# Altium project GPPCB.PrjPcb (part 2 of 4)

## Sheet Latch1.SchDoc: P.C. BOARD
size A2; Revision: A; SheetNumber: 0; SheetTotal: 0
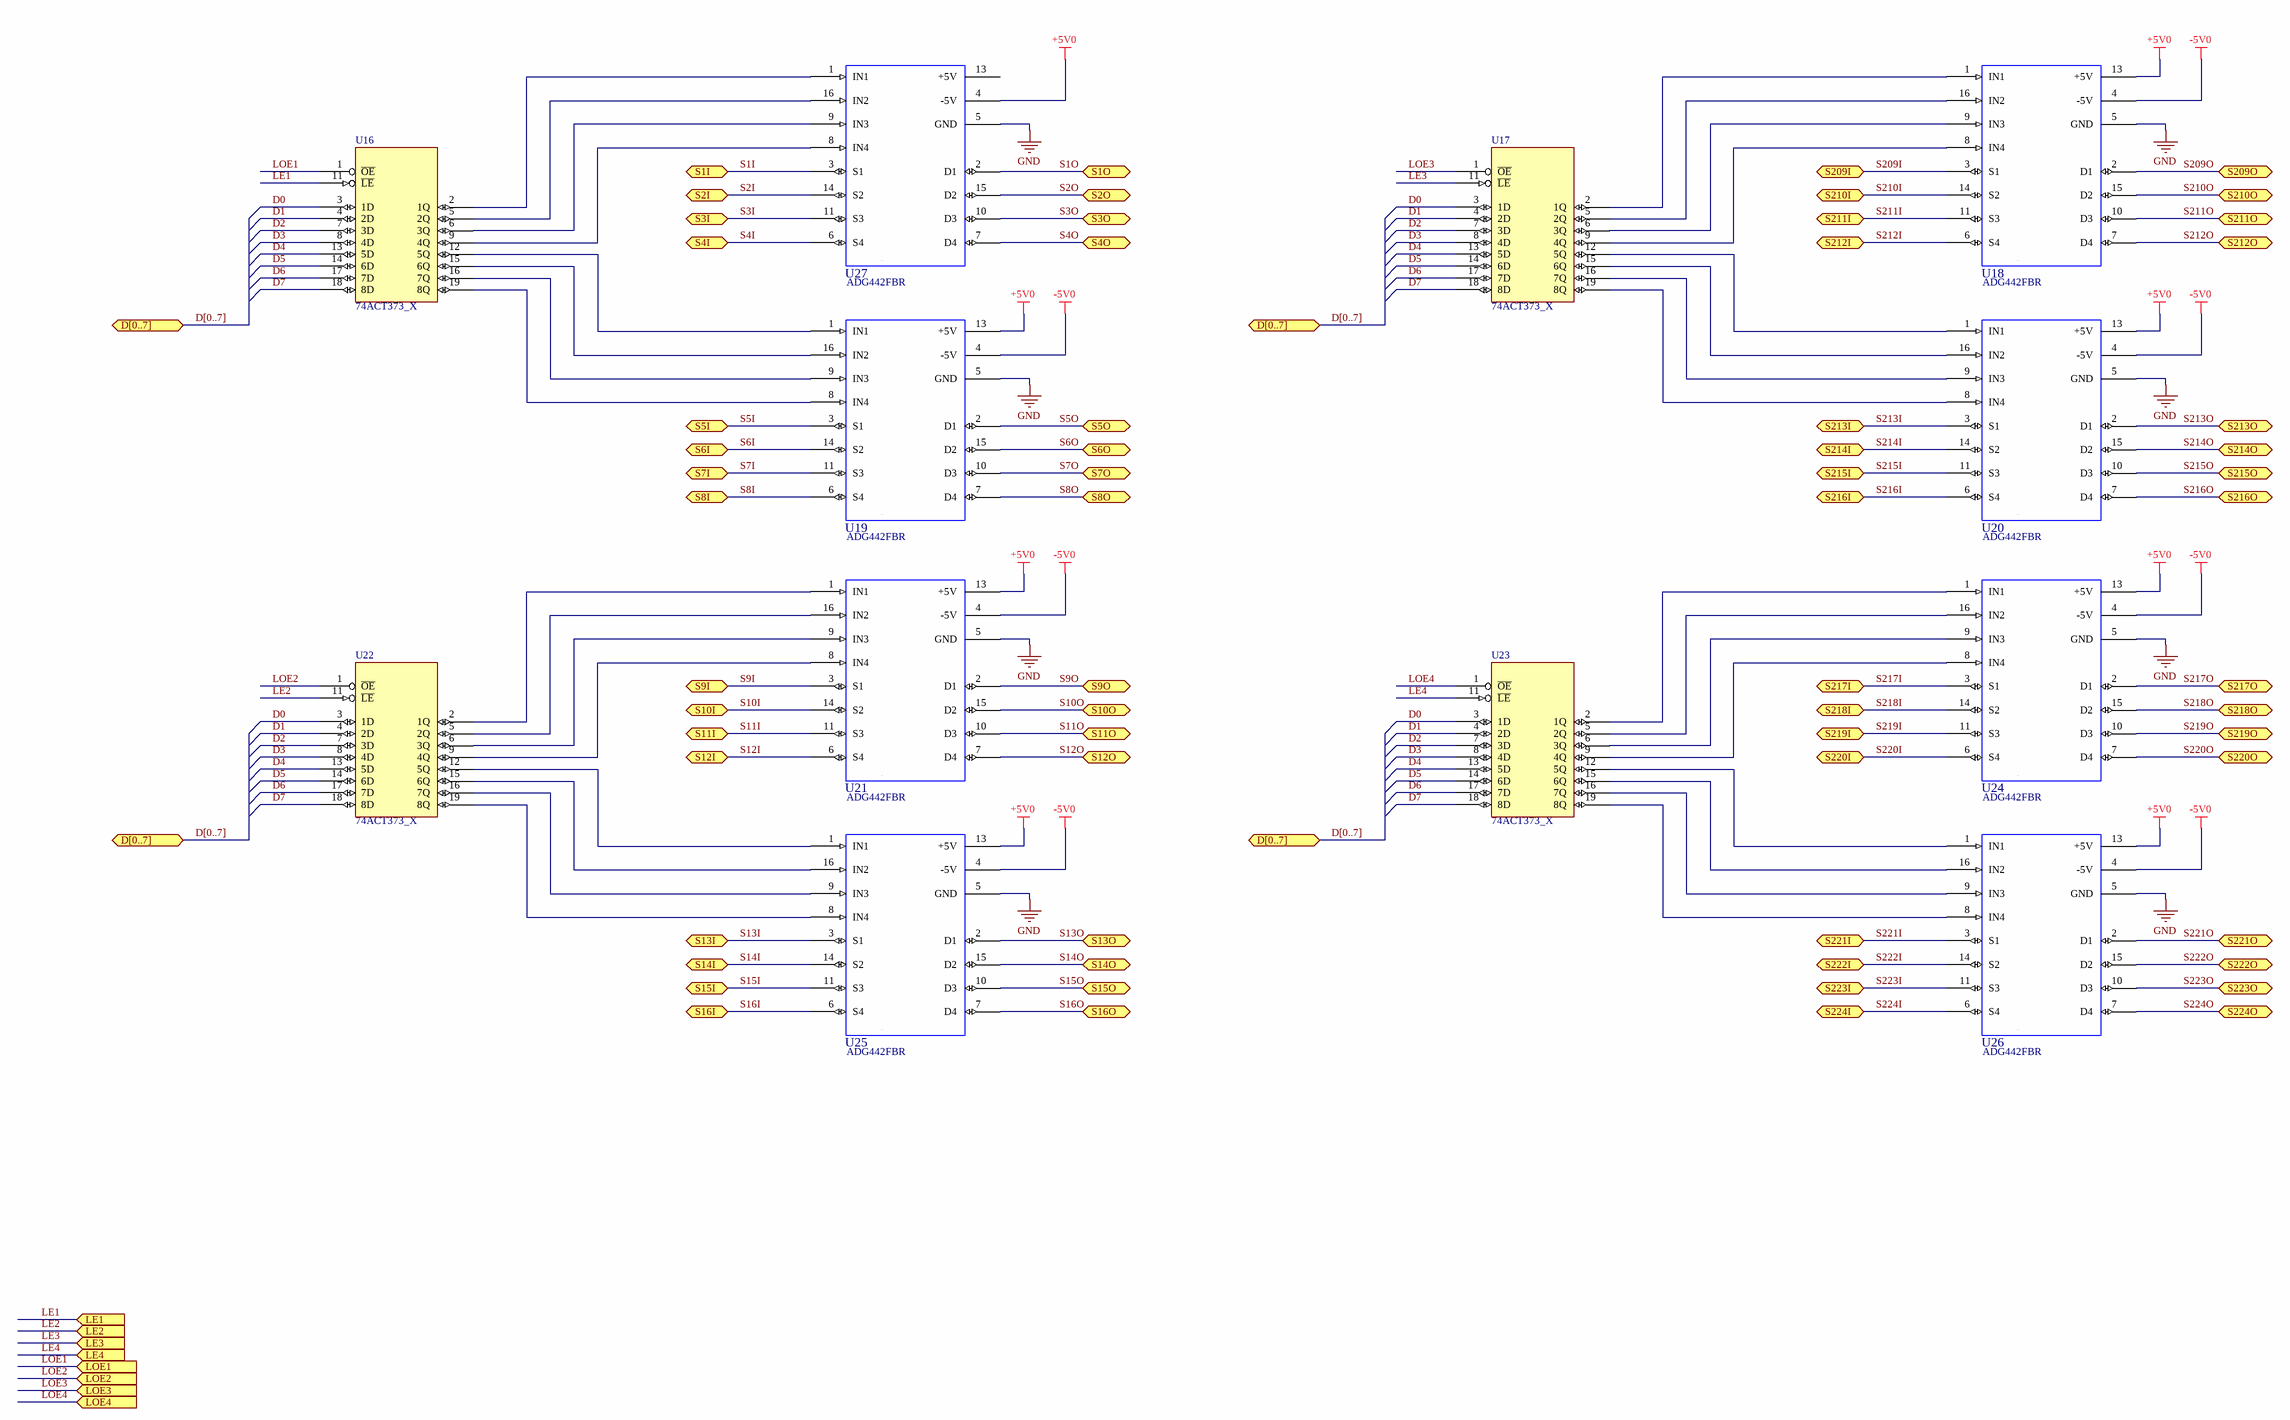
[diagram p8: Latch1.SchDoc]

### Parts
U16  74ACT373_X  [SOL-20/N]
U17  74ACT373_X  [SOL-20/N]
U18  VENDOR PART NO: ADG442FBR  [SO-16/N]  (hidden comment: ADG442)
U19  VENDOR PART NO: ADG442FBR  [SO-16/N]  (hidden comment: ADG442)
U20  VENDOR PART NO: ADG442FBR  [SO-16/N]  (hidden comment: ADG442)
U21  VENDOR PART NO: ADG442FBR  [SO-16/N]  (hidden comment: ADG442)
U22  74ACT373_X  [SOL-20/N]
U23  74ACT373_X  [SOL-20/N]
U24  VENDOR PART NO: ADG442FBR  [SO-16/N]  (hidden comment: ADG442)
U25  VENDOR PART NO: ADG442FBR  [SO-16/N]  (hidden comment: ADG442)
U26  VENDOR PART NO: ADG442FBR  [SO-16/N]  (hidden comment: ADG442)
U27  VENDOR PART NO: ADG442FBR  [SO-16/N]  (hidden comment: ADG442)

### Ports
D[0..7] (bidir), LE1 (in), LE2 (in), LE3 (in), LE4 (in), LOE1 (in), LOE2 (in), LOE3 (in), LOE4 (in), S1I (bidir), S1O (bidir), S2I (bidir), S2O (bidir), S3I (bidir), S3O (bidir), S4I (bidir), S4O (bidir), S5I (bidir), S5O (bidir), S6I (bidir), S6O (bidir), S7I (bidir), S7O (bidir), S8I (bidir), S8O (bidir), S9I (bidir), S9O (bidir), S10I (bidir), S10O (bidir), S11I (bidir), S11O (bidir), S12I (bidir), S12O (bidir), S13I (bidir), S13O (bidir), S14I (bidir), S14O (bidir), S15I (bidir), S15O (bidir), S16I (bidir), S16O (bidir), S209I (bidir), S209O (bidir), S210I (bidir), S210O (bidir), S211I (bidir), S211O (bidir), S212I (bidir), S212O (bidir), S213I (bidir), S213O (bidir), S214I (bidir), S214O (bidir), S215I (bidir), S215O (bidir), S216I (bidir), S216O (bidir), S217I (bidir), S217O (bidir), S218I (bidir), S218O (bidir), S219I (bidir), S219O (bidir), S220I (bidir), S220O (bidir), S221I (bidir), S221O (bidir), S222I (bidir), S222O (bidir), S223I (bidir), S223O (bidir), S224I (bidir), S224O (bidir)

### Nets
+5V0: U18.13(+5V) U19.13(+5V) U20.13(+5V) U21.13(+5V) U24.13(+5V) U25.13(+5V) U26.13(+5V) U27.4(-5V)
-5V0: U18.4(-5V) U19.4(-5V) U20.4(-5V) U21.4(-5V) U24.4(-5V) U25.4(-5V) U26.4(-5V)
GND: U18.5(GND) U19.5(GND) U20.5(GND) U21.5(GND) U24.5(GND) U25.5(GND) U26.5(GND) U27.5(GND)
D0: U16.3(1D) U17.3(1D) U22.3(1D) U23.3(1D)
D1: U16.4(2D) U17.4(2D) U22.4(2D) U23.4(2D)
D2: U16.7(3D) U17.7(3D) U22.7(3D) U23.7(3D)
D3: U16.8(4D) U17.8(4D) U22.8(4D) U23.8(4D)
D4: U16.13(5D) U17.13(5D) U22.13(5D) U23.13(5D)
D5: U16.14(6D) U17.14(6D) U22.14(6D) U23.14(6D)
D6: U16.17(7D) U17.17(7D) U22.17(7D) U23.17(7D)
D7: U16.18(8D) U17.18(8D) U22.18(8D) U23.18(8D)
LE1: U16.11(~{LE}) ; port LE1
LE2: U22.11(~{LE}) ; port LE2
LE3: U17.11(~{LE}) ; port LE3
LE4: U23.11(~{LE}) ; port LE4
LOE1: U16.1(~{OE}) ; port LOE1
LOE2: U22.1(~{OE}) ; port LOE2
LOE3: U17.1(~{OE}) ; port LOE3
LOE4: U23.1(~{OE}) ; port LOE4
S1I: U27.3(S1) ; port S1I
S1O: U27.2(D1) ; port S1O
S2I: U27.14(S2) ; port S2I
S2O: U27.15(D2) ; port S2O
S3I: U27.11(S3) ; port S3I
S3O: U27.10(D3) ; port S3O
S4I: U27.6(S4) ; port S4I
S4O: U27.7(D4) ; port S4O
S5I: U19.3(S1) ; port S5I
S5O: U19.2(D1) ; port S5O
S6I: U19.14(S2) ; port S6I
S6O: U19.15(D2) ; port S6O
S7I: U19.11(S3) ; port S7I
S7O: U19.10(D3) ; port S7O
S8I: U19.6(S4) ; port S8I
S8O: U19.7(D4) ; port S8O
S9I: U21.3(S1) ; port S9I
S9O: U21.2(D1) ; port S9O
S10I: U21.14(S2) ; port S10I
S10O: U21.15(D2) ; port S10O
S11I: U21.11(S3) ; port S11I
S11O: U21.10(D3) ; port S11O
S12I: U21.6(S4) ; port S12I
S12O: U21.7(D4) ; port S12O
S13I: U25.3(S1) ; port S13I
S13O: U25.2(D1) ; port S13O
S14I: U25.14(S2) ; port S14I
S14O: U25.15(D2) ; port S14O
S15I: U25.11(S3) ; port S15I
S15O: U25.10(D3) ; port S15O
S16I: U25.6(S4) ; port S16I
S16O: U25.7(D4) ; port S16O
S209I: U18.3(S1) ; port S209I
S209O: U18.2(D1) ; port S209O
S210I: U18.14(S2) ; port S210I
S210O: U18.15(D2) ; port S210O
S211I: U18.11(S3) ; port S211I
S211O: U18.10(D3) ; port S211O
S212I: U18.6(S4) ; port S212I
S212O: U18.7(D4) ; port S212O
S213I: U20.3(S1) ; port S213I
S213O: U20.2(D1) ; port S213O
S214I: U20.14(S2) ; port S214I
S214O: U20.15(D2) ; port S214O
S215I: U20.11(S3) ; port S215I
S215O: U20.10(D3) ; port S215O
S216I: U20.6(S4) ; port S216I
S216O: U20.7(D4) ; port S216O
S217I: U24.3(S1) ; port S217I
S217O: U24.2(D1) ; port S217O
S218I: U24.14(S2) ; port S218I
S218O: U24.15(D2) ; port S218O
S219I: U24.11(S3) ; port S219I
S219O: U24.10(D3) ; port S219O
S220I: U24.6(S4) ; port S220I
S220O: U24.7(D4) ; port S220O
S221I: U26.3(S1) ; port S221I
S221O: U26.2(D1) ; port S221O
S222I: U26.14(S2) ; port S222I
S222O: U26.15(D2) ; port S222O
S223I: U26.11(S3) ; port S223I
S223O: U26.10(D3) ; port S223O
S224I: U26.6(S4) ; port S224I
S224O: U26.7(D4) ; port S224O
NetU16_2: U16.2(1Q) U27.1(IN1)
NetU16_5: U16.5(2Q) U27.16(IN2)
NetU16_6: U16.6(3Q) U27.9(IN3)
NetU16_9: U16.9(4Q) U27.8(IN4)
NetU16_12: U16.12(5Q) U19.1(IN1)
NetU16_15: U16.15(6Q) U19.16(IN2)
NetU16_16: U16.16(7Q) U19.9(IN3)
NetU16_19: U16.19(8Q) U19.8(IN4)
NetU17_2: U17.2(1Q) U18.1(IN1)
NetU17_5: U17.5(2Q) U18.16(IN2)
NetU17_6: U17.6(3Q) U18.9(IN3)
NetU17_9: U17.9(4Q) U18.8(IN4)
NetU17_12: U17.12(5Q) U20.1(IN1)
NetU17_15: U17.15(6Q) U20.16(IN2)
NetU17_16: U17.16(7Q) U20.9(IN3)
NetU17_19: U17.19(8Q) U20.8(IN4)
NetU21_1: U21.1(IN1) U22.2(1Q)
NetU21_8: U21.8(IN4) U22.9(4Q)
NetU21_9: U21.9(IN3) U22.6(3Q)
NetU21_16: U21.16(IN2) U22.5(2Q)
NetU22_12: U22.12(5Q) U25.1(IN1)
NetU22_15: U22.15(6Q) U25.16(IN2)
NetU22_16: U22.16(7Q) U25.9(IN3)
NetU22_19: U22.19(8Q) U25.8(IN4)
NetU23_2: U23.2(1Q) U24.1(IN1)
NetU23_5: U23.5(2Q) U24.16(IN2)
NetU23_6: U23.6(3Q) U24.9(IN3)
NetU23_9: U23.9(4Q) U24.8(IN4)
NetU23_12: U23.12(5Q) U26.1(IN1)
NetU23_15: U23.15(6Q) U26.16(IN2)
NetU23_16: U23.16(7Q) U26.9(IN3)
NetU23_19: U23.19(8Q) U26.8(IN4)

Not connected (* = marked no-connect by the designer): U16 10(GND) 20(VCC); U17 10(GND) 20(VCC); U22 10(GND) 20(VCC); U23 10(GND) 20(VCC); U27 13(+5V)

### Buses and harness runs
bus D[0..7] = port D[0..7]

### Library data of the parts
U16 U17 U22 U23 = 74ACT373_X: IC, LATCH, OCTAL TRANSPARENT, TRISTATE; AMETEK PART NO: B1579-JP-001; AREA: 0.240; CHECKER: LEGACY PART
U18-U21 U24-U27 = ADG439FBR_X: IC, 8 channel,  Fault-Protected Analog Multiplexers; VENDOR: ANALOG DEVICES

## Sheet Latch2.SchDoc: P.C. BOARD
size A2; Revision: A; SheetNumber: 0; SheetTotal: 0
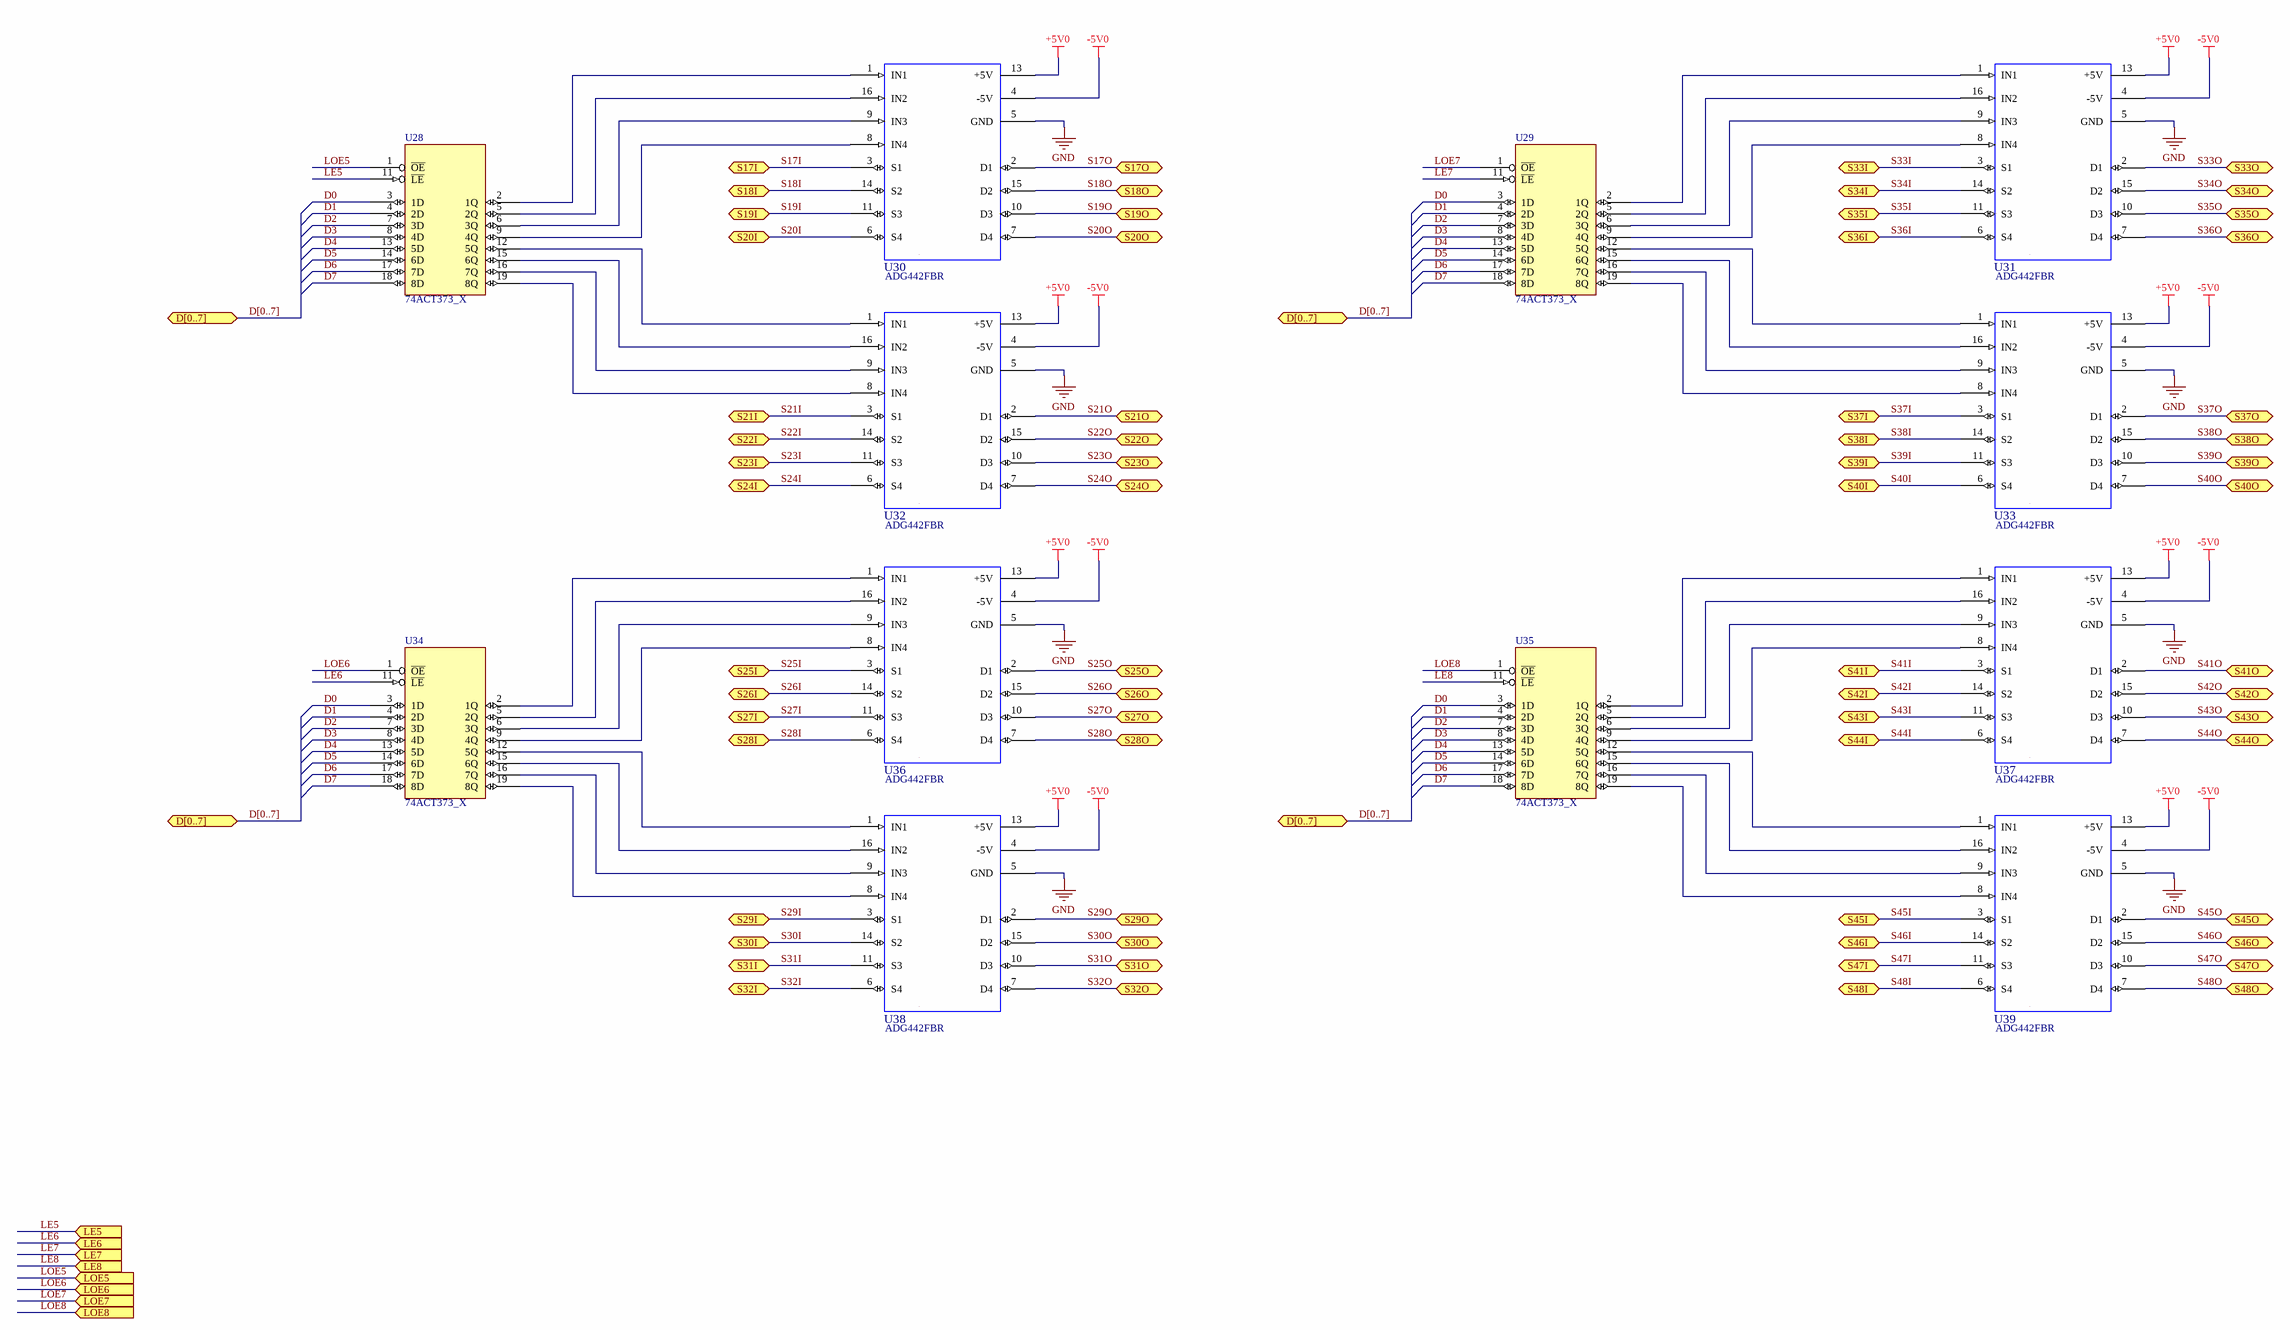
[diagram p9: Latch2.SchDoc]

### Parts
U28  74ACT373_X  [SOL-20/N]
U29  74ACT373_X  [SOL-20/N]
U30  VENDOR PART NO: ADG442FBR  [SO-16/N]  (hidden comment: ADG442)
U31  VENDOR PART NO: ADG442FBR  [SO-16/N]  (hidden comment: ADG442)
U32  VENDOR PART NO: ADG442FBR  [SO-16/N]  (hidden comment: ADG442)
U33  VENDOR PART NO: ADG442FBR  [SO-16/N]  (hidden comment: ADG442)
U34  74ACT373_X  [SOL-20/N]
U35  74ACT373_X  [SOL-20/N]
U36  VENDOR PART NO: ADG442FBR  [SO-16/N]  (hidden comment: ADG442)
U37  VENDOR PART NO: ADG442FBR  [SO-16/N]  (hidden comment: ADG442)
U38  VENDOR PART NO: ADG442FBR  [SO-16/N]  (hidden comment: ADG442)
U39  VENDOR PART NO: ADG442FBR  [SO-16/N]  (hidden comment: ADG442)

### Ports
D[0..7] (bidir), LE5 (in), LE6 (in), LE7 (in), LE8 (in), LOE5 (in), LOE6 (in), LOE7 (in), LOE8 (in), S17I (bidir), S17O (bidir), S18I (bidir), S18O (bidir), S19I (bidir), S19O (bidir), S20I (bidir), S20O (bidir), S21I (bidir), S21O (bidir), S22I (bidir), S22O (bidir), S23I (bidir), S23O (bidir), S24I (bidir), S24O (bidir), S25I (bidir), S25O (bidir), S26I (bidir), S26O (bidir), S27I (bidir), S27O (bidir), S28I (bidir), S28O (bidir), S29I (bidir), S29O (bidir), S30I (bidir), S30O (bidir), S31I (bidir), S31O (bidir), S32I (bidir), S32O (bidir), S33I (bidir), S33O (bidir), S34I (bidir), S34O (bidir), S35I (bidir), S35O (bidir), S36I (bidir), S36O (bidir), S37I (bidir), S37O (bidir), S38I (bidir), S38O (bidir), S39I (bidir), S39O (bidir), S40I (bidir), S40O (bidir), S41I (bidir), S41O (bidir), S42I (bidir), S42O (bidir), S43I (bidir), S43O (bidir), S44I (bidir), S44O (bidir), S45I (bidir), S45O (bidir), S46I (bidir), S46O (bidir), S47I (bidir), S47O (bidir), S48I (bidir), S48O (bidir)

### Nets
+5V0: U30.13(+5V) U31.13(+5V) U32.13(+5V) U33.13(+5V) U36.13(+5V) U37.13(+5V) U38.13(+5V) U39.13(+5V)
-5V0: U30.4(-5V) U31.4(-5V) U32.4(-5V) U33.4(-5V) U36.4(-5V) U37.4(-5V) U38.4(-5V) U39.4(-5V)
GND: U30.5(GND) U31.5(GND) U32.5(GND) U33.5(GND) U36.5(GND) U37.5(GND) U38.5(GND) U39.5(GND)
D0: U28.3(1D) U29.3(1D) U34.3(1D) U35.3(1D)
D1: U28.4(2D) U29.4(2D) U34.4(2D) U35.4(2D)
D2: U28.7(3D) U29.7(3D) U34.7(3D) U35.7(3D)
D3: U28.8(4D) U29.8(4D) U34.8(4D) U35.8(4D)
D4: U28.13(5D) U29.13(5D) U34.13(5D) U35.13(5D)
D5: U28.14(6D) U29.14(6D) U34.14(6D) U35.14(6D)
D6: U28.17(7D) U29.17(7D) U34.17(7D) U35.17(7D)
D7: U28.18(8D) U29.18(8D) U34.18(8D) U35.18(8D)
LE5: U28.11(~{LE}) ; port LE5
LE6: U34.11(~{LE}) ; port LE6
LE7: U29.11(~{LE}) ; port LE7
LE8: U35.11(~{LE}) ; port LE8
LOE5: U28.1(~{OE}) ; port LOE5
LOE6: U34.1(~{OE}) ; port LOE6
LOE7: U29.1(~{OE}) ; port LOE7
LOE8: U35.1(~{OE}) ; port LOE8
S17I: U30.3(S1) ; port S17I
S17O: U30.2(D1) ; port S17O
S18I: U30.14(S2) ; port S18I
S18O: U30.15(D2) ; port S18O
S19I: U30.11(S3) ; port S19I
S19O: U30.10(D3) ; port S19O
S20I: U30.6(S4) ; port S20I
S20O: U30.7(D4) ; port S20O
S21I: U32.3(S1) ; port S21I
S21O: U32.2(D1) ; port S21O
S22I: U32.14(S2) ; port S22I
S22O: U32.15(D2) ; port S22O
S23I: U32.11(S3) ; port S23I
S23O: U32.10(D3) ; port S23O
S24I: U32.6(S4) ; port S24I
S24O: U32.7(D4) ; port S24O
S25I: U36.3(S1) ; port S25I
S25O: U36.2(D1) ; port S25O
S26I: U36.14(S2) ; port S26I
S26O: U36.15(D2) ; port S26O
S27I: U36.11(S3) ; port S27I
S27O: U36.10(D3) ; port S27O
S28I: U36.6(S4) ; port S28I
S28O: U36.7(D4) ; port S28O
S29I: U38.3(S1) ; port S29I
S29O: U38.2(D1) ; port S29O
S30I: U38.14(S2) ; port S30I
S30O: U38.15(D2) ; port S30O
S31I: U38.11(S3) ; port S31I
S31O: U38.10(D3) ; port S31O
S32I: U38.6(S4) ; port S32I
S32O: U38.7(D4) ; port S32O
S33I: U31.3(S1) ; port S33I
S33O: U31.2(D1) ; port S33O
S34I: U31.14(S2) ; port S34I
S34O: U31.15(D2) ; port S34O
S35I: U31.11(S3) ; port S35I
S35O: U31.10(D3) ; port S35O
S36I: U31.6(S4) ; port S36I
S36O: U31.7(D4) ; port S36O
S37I: U33.3(S1) ; port S37I
S37O: U33.2(D1) ; port S37O
S38I: U33.14(S2) ; port S38I
S38O: U33.15(D2) ; port S38O
S39I: U33.11(S3) ; port S39I
S39O: U33.10(D3) ; port S39O
S40I: U33.6(S4) ; port S40I
S40O: U33.7(D4) ; port S40O
S41I: U37.3(S1) ; port S41I
S41O: U37.2(D1) ; port S41O
S42I: U37.14(S2) ; port S42I
S42O: U37.15(D2) ; port S42O
S43I: U37.11(S3) ; port S43I
S43O: U37.10(D3) ; port S43O
S44I: U37.6(S4) ; port S44I
S44O: U37.7(D4) ; port S44O
S45I: U39.3(S1) ; port S45I
S45O: U39.2(D1) ; port S45O
S46I: U39.14(S2) ; port S46I
S46O: U39.15(D2) ; port S46O
S47I: U39.11(S3) ; port S47I
S47O: U39.10(D3) ; port S47O
S48I: U39.6(S4) ; port S48I
S48O: U39.7(D4) ; port S48O
NetU28_2: U28.2(1Q) U30.1(IN1)
NetU28_5: U28.5(2Q) U30.16(IN2)
NetU28_6: U28.6(3Q) U30.9(IN3)
NetU28_9: U28.9(4Q) U30.8(IN4)
NetU28_12: U28.12(5Q) U32.1(IN1)
NetU28_15: U28.15(6Q) U32.16(IN2)
NetU28_16: U28.16(7Q) U32.9(IN3)
NetU28_19: U28.19(8Q) U32.8(IN4)
NetU29_2: U29.2(1Q) U31.1(IN1)
NetU29_5: U29.5(2Q) U31.16(IN2)
NetU29_6: U29.6(3Q) U31.9(IN3)
NetU29_9: U29.9(4Q) U31.8(IN4)
NetU29_12: U29.12(5Q) U33.1(IN1)
NetU29_15: U29.15(6Q) U33.16(IN2)
NetU29_16: U29.16(7Q) U33.9(IN3)
NetU29_19: U29.19(8Q) U33.8(IN4)
NetU34_2: U34.2(1Q) U36.1(IN1)
NetU34_5: U34.5(2Q) U36.16(IN2)
NetU34_6: U34.6(3Q) U36.9(IN3)
NetU34_9: U34.9(4Q) U36.8(IN4)
NetU34_12: U34.12(5Q) U38.1(IN1)
NetU34_15: U34.15(6Q) U38.16(IN2)
NetU34_16: U34.16(7Q) U38.9(IN3)
NetU34_19: U34.19(8Q) U38.8(IN4)
NetU35_2: U35.2(1Q) U37.1(IN1)
NetU35_5: U35.5(2Q) U37.16(IN2)
NetU35_6: U35.6(3Q) U37.9(IN3)
NetU35_9: U35.9(4Q) U37.8(IN4)
NetU35_12: U35.12(5Q) U39.1(IN1)
NetU35_15: U35.15(6Q) U39.16(IN2)
NetU35_16: U35.16(7Q) U39.9(IN3)
NetU35_19: U35.19(8Q) U39.8(IN4)

Not connected (* = marked no-connect by the designer): U28 10(GND) 20(VCC); U29 10(GND) 20(VCC); U34 10(GND) 20(VCC); U35 10(GND) 20(VCC)

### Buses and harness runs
bus D[0..7] = port D[0..7]

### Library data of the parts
U28 U29 U34 U35 = 74ACT373_X: as U16 on sheet Latch1
U30-U33 U36-U39 = ADG439FBR_X: as U18 on sheet Latch1

## Sheet Latch3.SchDoc: P.C. BOARD
size A2; Revision: A; SheetNumber: 0; SheetTotal: 0
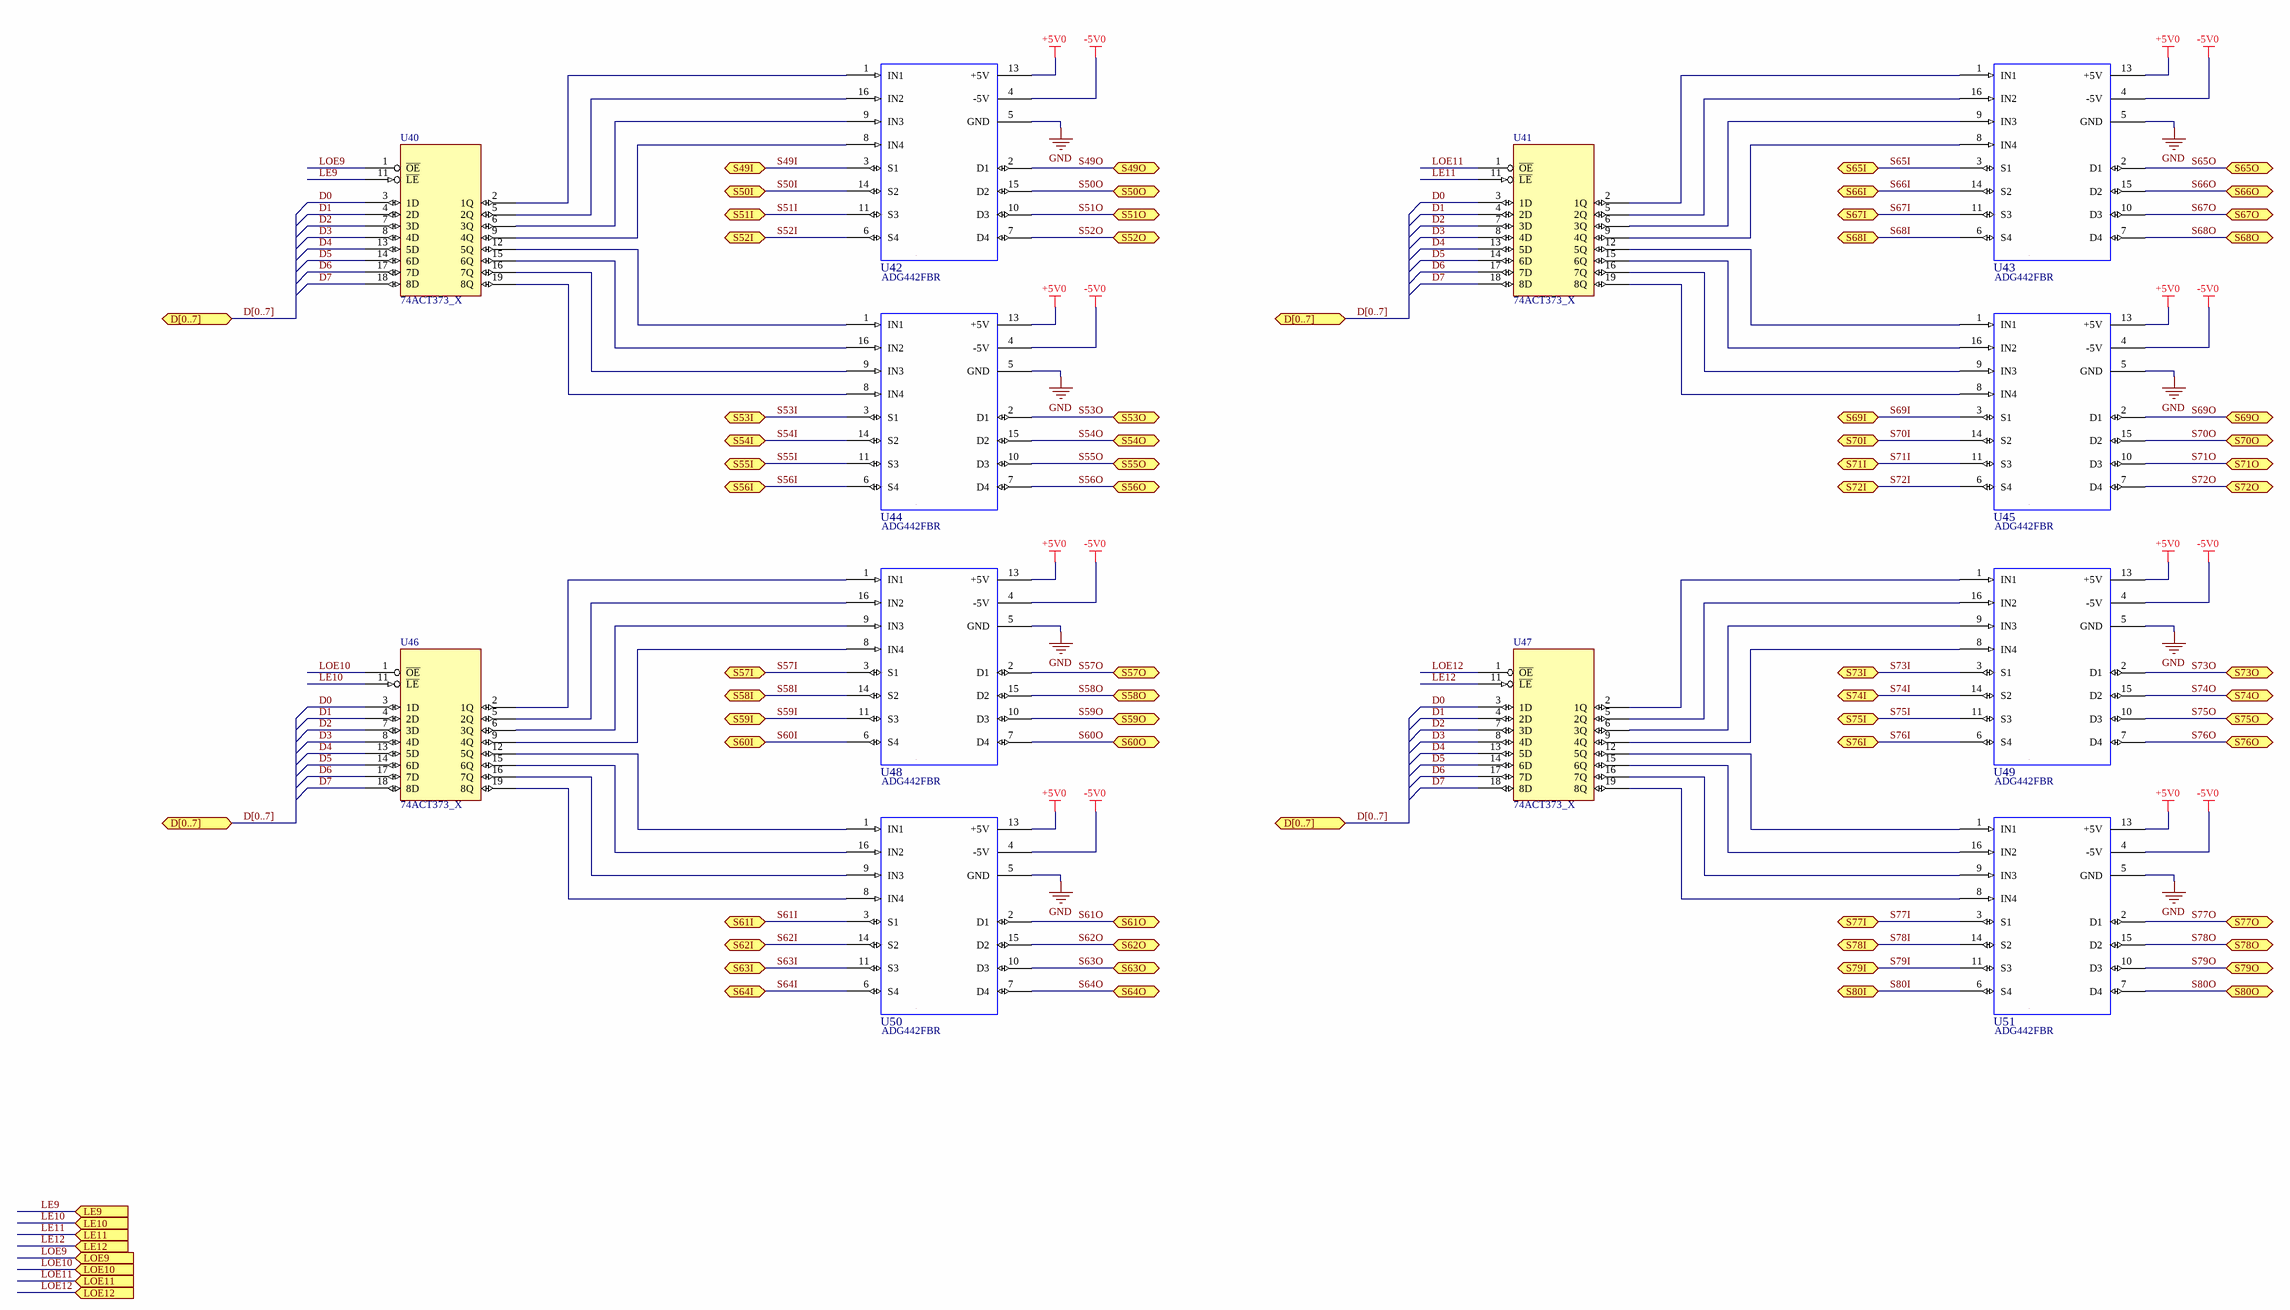
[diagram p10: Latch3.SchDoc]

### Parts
U40  74ACT373_X  [SOL-20/N]
U41  74ACT373_X  [SOL-20/N]
U42  VENDOR PART NO: ADG442FBR  [SO-16/N]  (hidden comment: ADG442)
U43  VENDOR PART NO: ADG442FBR  [SO-16/N]  (hidden comment: ADG442)
U44  VENDOR PART NO: ADG442FBR  [SO-16/N]  (hidden comment: ADG442)
U45  VENDOR PART NO: ADG442FBR  [SO-16/N]  (hidden comment: ADG442)
U46  74ACT373_X  [SOL-20/N]
U47  74ACT373_X  [SOL-20/N]
U48  VENDOR PART NO: ADG442FBR  [SO-16/N]  (hidden comment: ADG442)
U49  VENDOR PART NO: ADG442FBR  [SO-16/N]  (hidden comment: ADG442)
U50  VENDOR PART NO: ADG442FBR  [SO-16/N]  (hidden comment: ADG442)
U51  VENDOR PART NO: ADG442FBR  [SO-16/N]  (hidden comment: ADG442)

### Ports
D[0..7] (bidir), LE9 (in), LE10 (in), LE11 (in), LE12 (in), LOE9 (in), LOE10 (in), LOE11 (in), LOE12 (in), S49I (bidir), S49O (bidir), S50I (bidir), S50O (bidir), S51I (bidir), S51O (bidir), S52I (bidir), S52O (bidir), S53I (bidir), S53O (bidir), S54I (bidir), S54O (bidir), S55I (bidir), S55O (bidir), S56I (bidir), S56O (bidir), S57I (bidir), S57O (bidir), S58I (bidir), S58O (bidir), S59I (bidir), S59O (bidir), S60I (bidir), S60O (bidir), S61I (bidir), S61O (bidir), S62I (bidir), S62O (bidir), S63I (bidir), S63O (bidir), S64I (bidir), S64O (bidir), S65I (bidir), S65O (bidir), S66I (bidir), S66O (bidir), S67I (bidir), S67O (bidir), S68I (bidir), S68O (bidir), S69I (bidir), S69O (bidir), S70I (bidir), S70O (bidir), S71I (bidir), S71O (bidir), S72I (bidir), S72O (bidir), S73I (bidir), S73O (bidir), S74I (bidir), S74O (bidir), S75I (bidir), S75O (bidir), S76I (bidir), S76O (bidir), S77I (bidir), S77O (bidir), S78I (bidir), S78O (bidir), S79I (bidir), S79O (bidir), S80I (bidir), S80O (bidir)

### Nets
+5V0: U42.13(+5V) U43.13(+5V) U44.13(+5V) U45.13(+5V) U48.13(+5V) U49.13(+5V) U50.13(+5V) U51.13(+5V)
-5V0: U42.4(-5V) U43.4(-5V) U44.4(-5V) U45.4(-5V) U48.4(-5V) U49.4(-5V) U50.4(-5V) U51.4(-5V)
GND: U42.5(GND) U43.5(GND) U44.5(GND) U45.5(GND) U48.5(GND) U49.5(GND) U50.5(GND) U51.5(GND)
D0: U40.3(1D) U41.3(1D) U46.3(1D) U47.3(1D)
D1: U40.4(2D) U41.4(2D) U46.4(2D) U47.4(2D)
D2: U40.7(3D) U41.7(3D) U46.7(3D) U47.7(3D)
D3: U40.8(4D) U41.8(4D) U46.8(4D) U47.8(4D)
D4: U40.13(5D) U41.13(5D) U46.13(5D) U47.13(5D)
D5: U40.14(6D) U41.14(6D) U46.14(6D) U47.14(6D)
D6: U40.17(7D) U41.17(7D) U46.17(7D) U47.17(7D)
D7: U40.18(8D) U41.18(8D) U46.18(8D) U47.18(8D)
LE9: U40.11(~{LE}) ; port LE9
LE10: U46.11(~{LE}) ; port LE10
LE11: U41.11(~{LE}) ; port LE11
LE12: U47.11(~{LE}) ; port LE12
LOE9: U40.1(~{OE}) ; port LOE9
LOE10: U46.1(~{OE}) ; port LOE10
LOE11: U41.1(~{OE}) ; port LOE11
LOE12: U47.1(~{OE}) ; port LOE12
S49I: U42.3(S1) ; port S49I
S49O: U42.2(D1) ; port S49O
S50I: U42.14(S2) ; port S50I
S50O: U42.15(D2) ; port S50O
S51I: U42.11(S3) ; port S51I
S51O: U42.10(D3) ; port S51O
S52I: U42.6(S4) ; port S52I
S52O: U42.7(D4) ; port S52O
S53I: U44.3(S1) ; port S53I
S53O: U44.2(D1) ; port S53O
S54I: U44.14(S2) ; port S54I
S54O: U44.15(D2) ; port S54O
S55I: U44.11(S3) ; port S55I
S55O: U44.10(D3) ; port S55O
S56I: U44.6(S4) ; port S56I
S56O: U44.7(D4) ; port S56O
S57I: U48.3(S1) ; port S57I
S57O: U48.2(D1) ; port S57O
S58I: U48.14(S2) ; port S58I
S58O: U48.15(D2) ; port S58O
S59I: U48.11(S3) ; port S59I
S59O: U48.10(D3) ; port S59O
S60I: U48.6(S4) ; port S60I
S60O: U48.7(D4) ; port S60O
S61I: U50.3(S1) ; port S61I
S61O: U50.2(D1) ; port S61O
S62I: U50.14(S2) ; port S62I
S62O: U50.15(D2) ; port S62O
S63I: U50.11(S3) ; port S63I
S63O: U50.10(D3) ; port S63O
S64I: U50.6(S4) ; port S64I
S64O: U50.7(D4) ; port S64O
S65I: U43.3(S1) ; port S65I
S65O: U43.2(D1) ; port S65O
S66I: U43.14(S2) ; port S66I
S66O: U43.15(D2) ; port S66O
S67I: U43.11(S3) ; port S67I
S67O: U43.10(D3) ; port S67O
S68I: U43.6(S4) ; port S68I
S68O: U43.7(D4) ; port S68O
S69I: U45.3(S1) ; port S69I
S69O: U45.2(D1) ; port S69O
S70I: U45.14(S2) ; port S70I
S70O: U45.15(D2) ; port S70O
S71I: U45.11(S3) ; port S71I
S71O: U45.10(D3) ; port S71O
S72I: U45.6(S4) ; port S72I
S72O: U45.7(D4) ; port S72O
S73I: U49.3(S1) ; port S73I
S73O: U49.2(D1) ; port S73O
S74I: U49.14(S2) ; port S74I
S74O: U49.15(D2) ; port S74O
S75I: U49.11(S3) ; port S75I
S75O: U49.10(D3) ; port S75O
S76I: U49.6(S4) ; port S76I
S76O: U49.7(D4) ; port S76O
S77I: U51.3(S1) ; port S77I
S77O: U51.2(D1) ; port S77O
S78I: U51.14(S2) ; port S78I
S78O: U51.15(D2) ; port S78O
S79I: U51.11(S3) ; port S79I
S79O: U51.10(D3) ; port S79O
S80I: U51.6(S4) ; port S80I
S80O: U51.7(D4) ; port S80O
NetU40_2: U40.2(1Q) U42.1(IN1)
NetU40_5: U40.5(2Q) U42.16(IN2)
NetU40_6: U40.6(3Q) U42.9(IN3)
NetU40_9: U40.9(4Q) U42.8(IN4)
NetU40_12: U40.12(5Q) U44.1(IN1)
NetU40_15: U40.15(6Q) U44.16(IN2)
NetU40_16: U40.16(7Q) U44.9(IN3)
NetU40_19: U40.19(8Q) U44.8(IN4)
NetU41_2: U41.2(1Q) U43.1(IN1)
NetU41_5: U41.5(2Q) U43.16(IN2)
NetU41_6: U41.6(3Q) U43.9(IN3)
NetU41_9: U41.9(4Q) U43.8(IN4)
NetU41_12: U41.12(5Q) U45.1(IN1)
NetU41_15: U41.15(6Q) U45.16(IN2)
NetU41_16: U41.16(7Q) U45.9(IN3)
NetU41_19: U41.19(8Q) U45.8(IN4)
NetU46_2: U46.2(1Q) U48.1(IN1)
NetU46_5: U46.5(2Q) U48.16(IN2)
NetU46_6: U46.6(3Q) U48.9(IN3)
NetU46_9: U46.9(4Q) U48.8(IN4)
NetU46_12: U46.12(5Q) U50.1(IN1)
NetU46_15: U46.15(6Q) U50.16(IN2)
NetU46_16: U46.16(7Q) U50.9(IN3)
NetU46_19: U46.19(8Q) U50.8(IN4)
NetU47_2: U47.2(1Q) U49.1(IN1)
NetU47_5: U47.5(2Q) U49.16(IN2)
NetU47_6: U47.6(3Q) U49.9(IN3)
NetU47_9: U47.9(4Q) U49.8(IN4)
NetU47_12: U47.12(5Q) U51.1(IN1)
NetU47_15: U47.15(6Q) U51.16(IN2)
NetU47_16: U47.16(7Q) U51.9(IN3)
NetU47_19: U47.19(8Q) U51.8(IN4)

Not connected (* = marked no-connect by the designer): U40 10(GND) 20(VCC); U41 10(GND) 20(VCC); U46 10(GND) 20(VCC); U47 10(GND) 20(VCC)

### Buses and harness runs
bus D[0..7] = port D[0..7]

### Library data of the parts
U40 U41 U46 U47 = 74ACT373_X: as U16 on sheet Latch1
U42-U45 U48-U51 = ADG439FBR_X: as U18 on sheet Latch1

## Sheet Latch4.SchDoc: P.C. BOARD
size A2; Revision: A; SheetNumber: 0; SheetTotal: 0
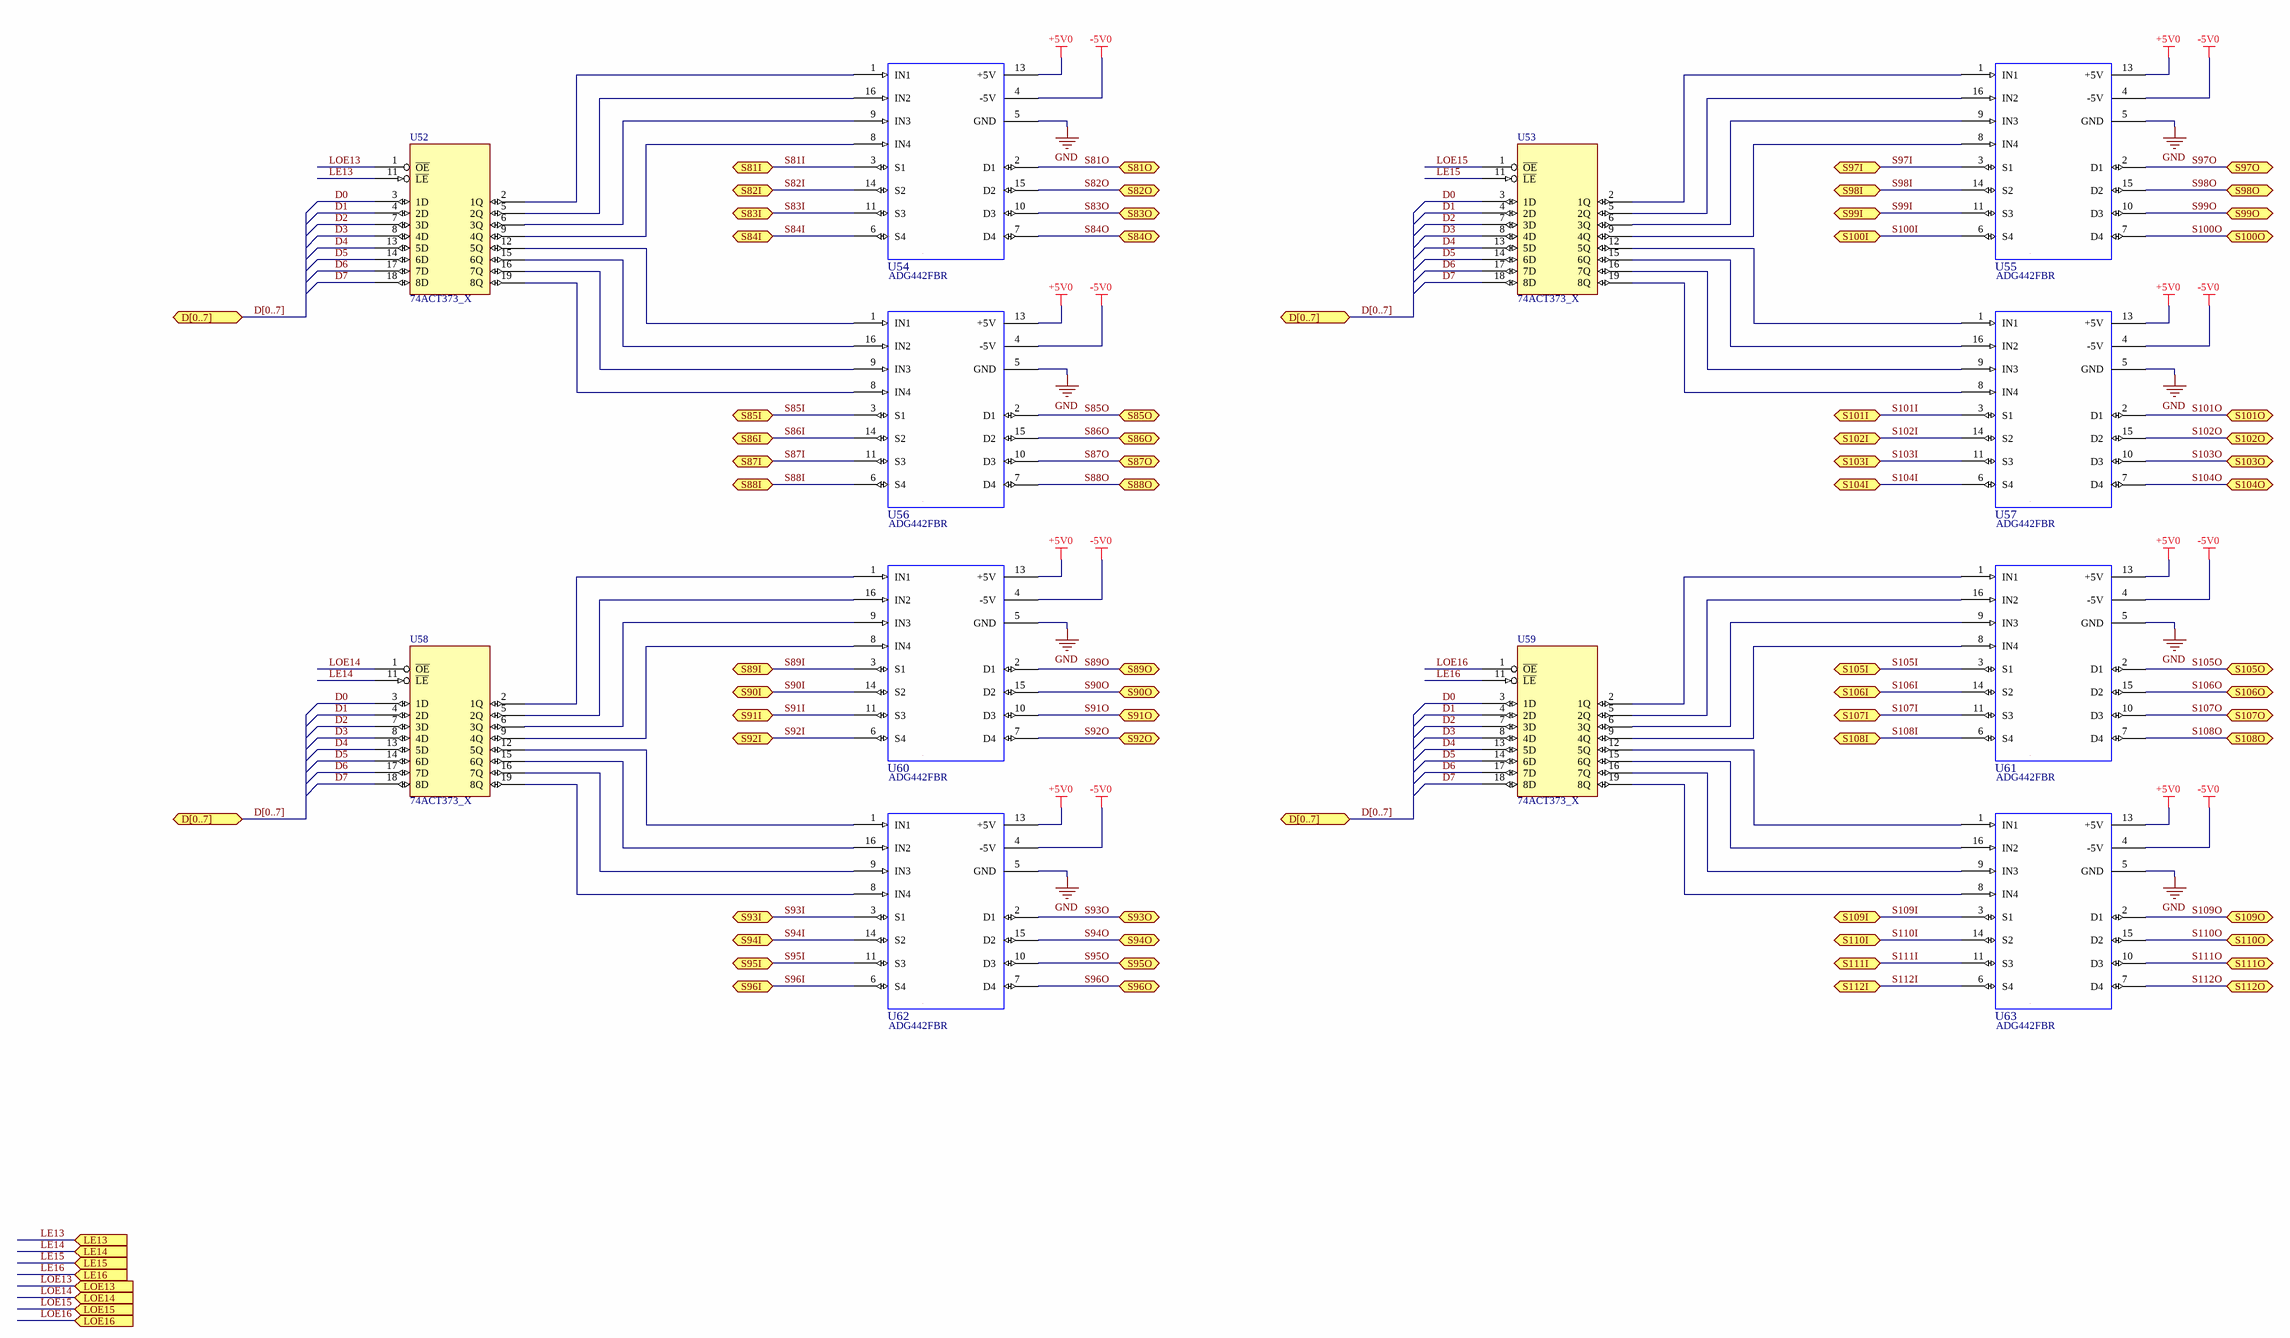
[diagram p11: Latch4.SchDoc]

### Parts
U52  74ACT373_X  [SOL-20/N]
U53  74ACT373_X  [SOL-20/N]
U54  VENDOR PART NO: ADG442FBR  [SO-16/N]  (hidden comment: ADG442)
U55  VENDOR PART NO: ADG442FBR  [SO-16/N]  (hidden comment: ADG442)
U56  VENDOR PART NO: ADG442FBR  [SO-16/N]  (hidden comment: ADG442)
U57  VENDOR PART NO: ADG442FBR  [SO-16/N]  (hidden comment: ADG442)
U58  74ACT373_X  [SOL-20/N]
U59  74ACT373_X  [SOL-20/N]
U60  VENDOR PART NO: ADG442FBR  [SO-16/N]  (hidden comment: ADG442)
U61  VENDOR PART NO: ADG442FBR  [SO-16/N]  (hidden comment: ADG442)
U62  VENDOR PART NO: ADG442FBR  [SO-16/N]  (hidden comment: ADG442)
U63  VENDOR PART NO: ADG442FBR  [SO-16/N]  (hidden comment: ADG442)

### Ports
D[0..7] (bidir), LE13 (in), LE14 (in), LE15 (in), LE16 (in), LOE13 (in), LOE14 (in), LOE15 (in), LOE16 (in), S81I (bidir), S81O (bidir), S82I (bidir), S82O (bidir), S83I (bidir), S83O (bidir), S84I (bidir), S84O (bidir), S85I (bidir), S85O (bidir), S86I (bidir), S86O (bidir), S87I (bidir), S87O (bidir), S88I (bidir), S88O (bidir), S89I (bidir), S89O (bidir), S90I (bidir), S90O (bidir), S91I (bidir), S91O (bidir), S92I (bidir), S92O (bidir), S93I (bidir), S93O (bidir), S94I (bidir), S94O (bidir), S95I (bidir), S95O (bidir), S96I (bidir), S96O (bidir), S97I (bidir), S97O (bidir), S98I (bidir), S98O (bidir), S99I (bidir), S99O (bidir), S100I (bidir), S100O (bidir), S101I (bidir), S101O (bidir), S102I (bidir), S102O (bidir), S103I (bidir), S103O (bidir), S104I (bidir), S104O (bidir), S105I (bidir), S105O (bidir), S106I (bidir), S106O (bidir), S107I (bidir), S107O (bidir), S108I (bidir), S108O (bidir), S109I (bidir), S109O (bidir), S110I (bidir), S110O (bidir), S111I (bidir), S111O (bidir), S112I (bidir), S112O (bidir)

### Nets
+5V0: U54.13(+5V) U55.13(+5V) U56.13(+5V) U57.13(+5V) U60.13(+5V) U61.13(+5V) U62.13(+5V) U63.13(+5V)
-5V0: U54.4(-5V) U55.4(-5V) U56.4(-5V) U57.4(-5V) U60.4(-5V) U61.4(-5V) U62.4(-5V) U63.4(-5V)
GND: U54.5(GND) U55.5(GND) U56.5(GND) U57.5(GND) U60.5(GND) U61.5(GND) U62.5(GND) U63.5(GND)
D0: U52.3(1D) U53.3(1D) U58.3(1D) U59.3(1D)
D1: U52.4(2D) U53.4(2D) U58.4(2D) U59.4(2D)
D2: U52.7(3D) U53.7(3D) U58.7(3D) U59.7(3D)
D3: U52.8(4D) U53.8(4D) U58.8(4D) U59.8(4D)
D4: U52.13(5D) U53.13(5D) U58.13(5D) U59.13(5D)
D5: U52.14(6D) U53.14(6D) U58.14(6D) U59.14(6D)
D6: U52.17(7D) U53.17(7D) U58.17(7D) U59.17(7D)
D7: U52.18(8D) U53.18(8D) U58.18(8D) U59.18(8D)
LE13: U52.11(~{LE}) ; port LE13
LE14: U58.11(~{LE}) ; port LE14
LE15: U53.11(~{LE}) ; port LE15
LE16: U59.11(~{LE}) ; port LE16
LOE13: U52.1(~{OE}) ; port LOE13
LOE14: U58.1(~{OE}) ; port LOE14
LOE15: U53.1(~{OE}) ; port LOE15
LOE16: U59.1(~{OE}) ; port LOE16
S81I: U54.3(S1) ; port S81I
S81O: U54.2(D1) ; port S81O
S82I: U54.14(S2) ; port S82I
S82O: U54.15(D2) ; port S82O
S83I: U54.11(S3) ; port S83I
S83O: U54.10(D3) ; port S83O
S84I: U54.6(S4) ; port S84I
S84O: U54.7(D4) ; port S84O
S85I: U56.3(S1) ; port S85I
S85O: U56.2(D1) ; port S85O
S86I: U56.14(S2) ; port S86I
S86O: U56.15(D2) ; port S86O
S87I: U56.11(S3) ; port S87I
S87O: U56.10(D3) ; port S87O
S88I: U56.6(S4) ; port S88I
S88O: U56.7(D4) ; port S88O
S89I: U60.3(S1) ; port S89I
S89O: U60.2(D1) ; port S89O
S90I: U60.14(S2) ; port S90I
S90O: U60.15(D2) ; port S90O
S91I: U60.11(S3) ; port S91I
S91O: U60.10(D3) ; port S91O
S92I: U60.6(S4) ; port S92I
S92O: U60.7(D4) ; port S92O
S93I: U62.3(S1) ; port S93I
S93O: U62.2(D1) ; port S93O
S94I: U62.14(S2) ; port S94I
S94O: U62.15(D2) ; port S94O
S95I: U62.11(S3) ; port S95I
S95O: U62.10(D3) ; port S95O
S96I: U62.6(S4) ; port S96I
S96O: U62.7(D4) ; port S96O
S97I: U55.3(S1) ; port S97I
S97O: U55.2(D1) ; port S97O
S98I: U55.14(S2) ; port S98I
S98O: U55.15(D2) ; port S98O
S99I: U55.11(S3) ; port S99I
S99O: U55.10(D3) ; port S99O
S100I: U55.6(S4) ; port S100I
S100O: U55.7(D4) ; port S100O
S101I: U57.3(S1) ; port S101I
S101O: U57.2(D1) ; port S101O
S102I: U57.14(S2) ; port S102I
S102O: U57.15(D2) ; port S102O
S103I: U57.11(S3) ; port S103I
S103O: U57.10(D3) ; port S103O
S104I: U57.6(S4) ; port S104I
S104O: U57.7(D4) ; port S104O
S105I: U61.3(S1) ; port S105I
S105O: U61.2(D1) ; port S105O
S106I: U61.14(S2) ; port S106I
S106O: U61.15(D2) ; port S106O
S107I: U61.11(S3) ; port S107I
S107O: U61.10(D3) ; port S107O
S108I: U61.6(S4) ; port S108I
S108O: U61.7(D4) ; port S108O
S109I: U63.3(S1) ; port S109I
S109O: U63.2(D1) ; port S109O
S110I: U63.14(S2) ; port S110I
S110O: U63.15(D2) ; port S110O
S111I: U63.11(S3) ; port S111I
S111O: U63.10(D3) ; port S111O
S112I: U63.6(S4) ; port S112I
S112O: U63.7(D4) ; port S112O
NetU52_2: U52.2(1Q) U54.1(IN1)
NetU52_5: U52.5(2Q) U54.16(IN2)
NetU52_6: U52.6(3Q) U54.9(IN3)
NetU52_9: U52.9(4Q) U54.8(IN4)
NetU52_12: U52.12(5Q) U56.1(IN1)
NetU52_15: U52.15(6Q) U56.16(IN2)
NetU52_16: U52.16(7Q) U56.9(IN3)
NetU52_19: U52.19(8Q) U56.8(IN4)
NetU53_2: U53.2(1Q) U55.1(IN1)
NetU53_5: U53.5(2Q) U55.16(IN2)
NetU53_6: U53.6(3Q) U55.9(IN3)
NetU53_9: U53.9(4Q) U55.8(IN4)
NetU53_12: U53.12(5Q) U57.1(IN1)
NetU53_15: U53.15(6Q) U57.16(IN2)
NetU53_16: U53.16(7Q) U57.9(IN3)
NetU53_19: U53.19(8Q) U57.8(IN4)
NetU58_2: U58.2(1Q) U60.1(IN1)
NetU58_5: U58.5(2Q) U60.16(IN2)
NetU58_6: U58.6(3Q) U60.9(IN3)
NetU58_9: U58.9(4Q) U60.8(IN4)
NetU58_12: U58.12(5Q) U62.1(IN1)
NetU58_15: U58.15(6Q) U62.16(IN2)
NetU58_16: U58.16(7Q) U62.9(IN3)
NetU58_19: U58.19(8Q) U62.8(IN4)
NetU59_2: U59.2(1Q) U61.1(IN1)
NetU59_5: U59.5(2Q) U61.16(IN2)
NetU59_6: U59.6(3Q) U61.9(IN3)
NetU59_9: U59.9(4Q) U61.8(IN4)
NetU59_12: U59.12(5Q) U63.1(IN1)
NetU59_15: U59.15(6Q) U63.16(IN2)
NetU59_16: U59.16(7Q) U63.9(IN3)
NetU59_19: U59.19(8Q) U63.8(IN4)

Not connected (* = marked no-connect by the designer): U52 10(GND) 20(VCC); U53 10(GND) 20(VCC); U58 10(GND) 20(VCC); U59 10(GND) 20(VCC)

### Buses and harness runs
bus D[0..7] = port D[0..7]

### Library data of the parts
U52 U53 U58 U59 = 74ACT373_X: as U16 on sheet Latch1
U54-U57 U60-U63 = ADG439FBR_X: as U18 on sheet Latch1

## Sheet Latch5.SchDoc: P.C. BOARD
size A2; Revision: A; SheetNumber: 0; SheetTotal: 0
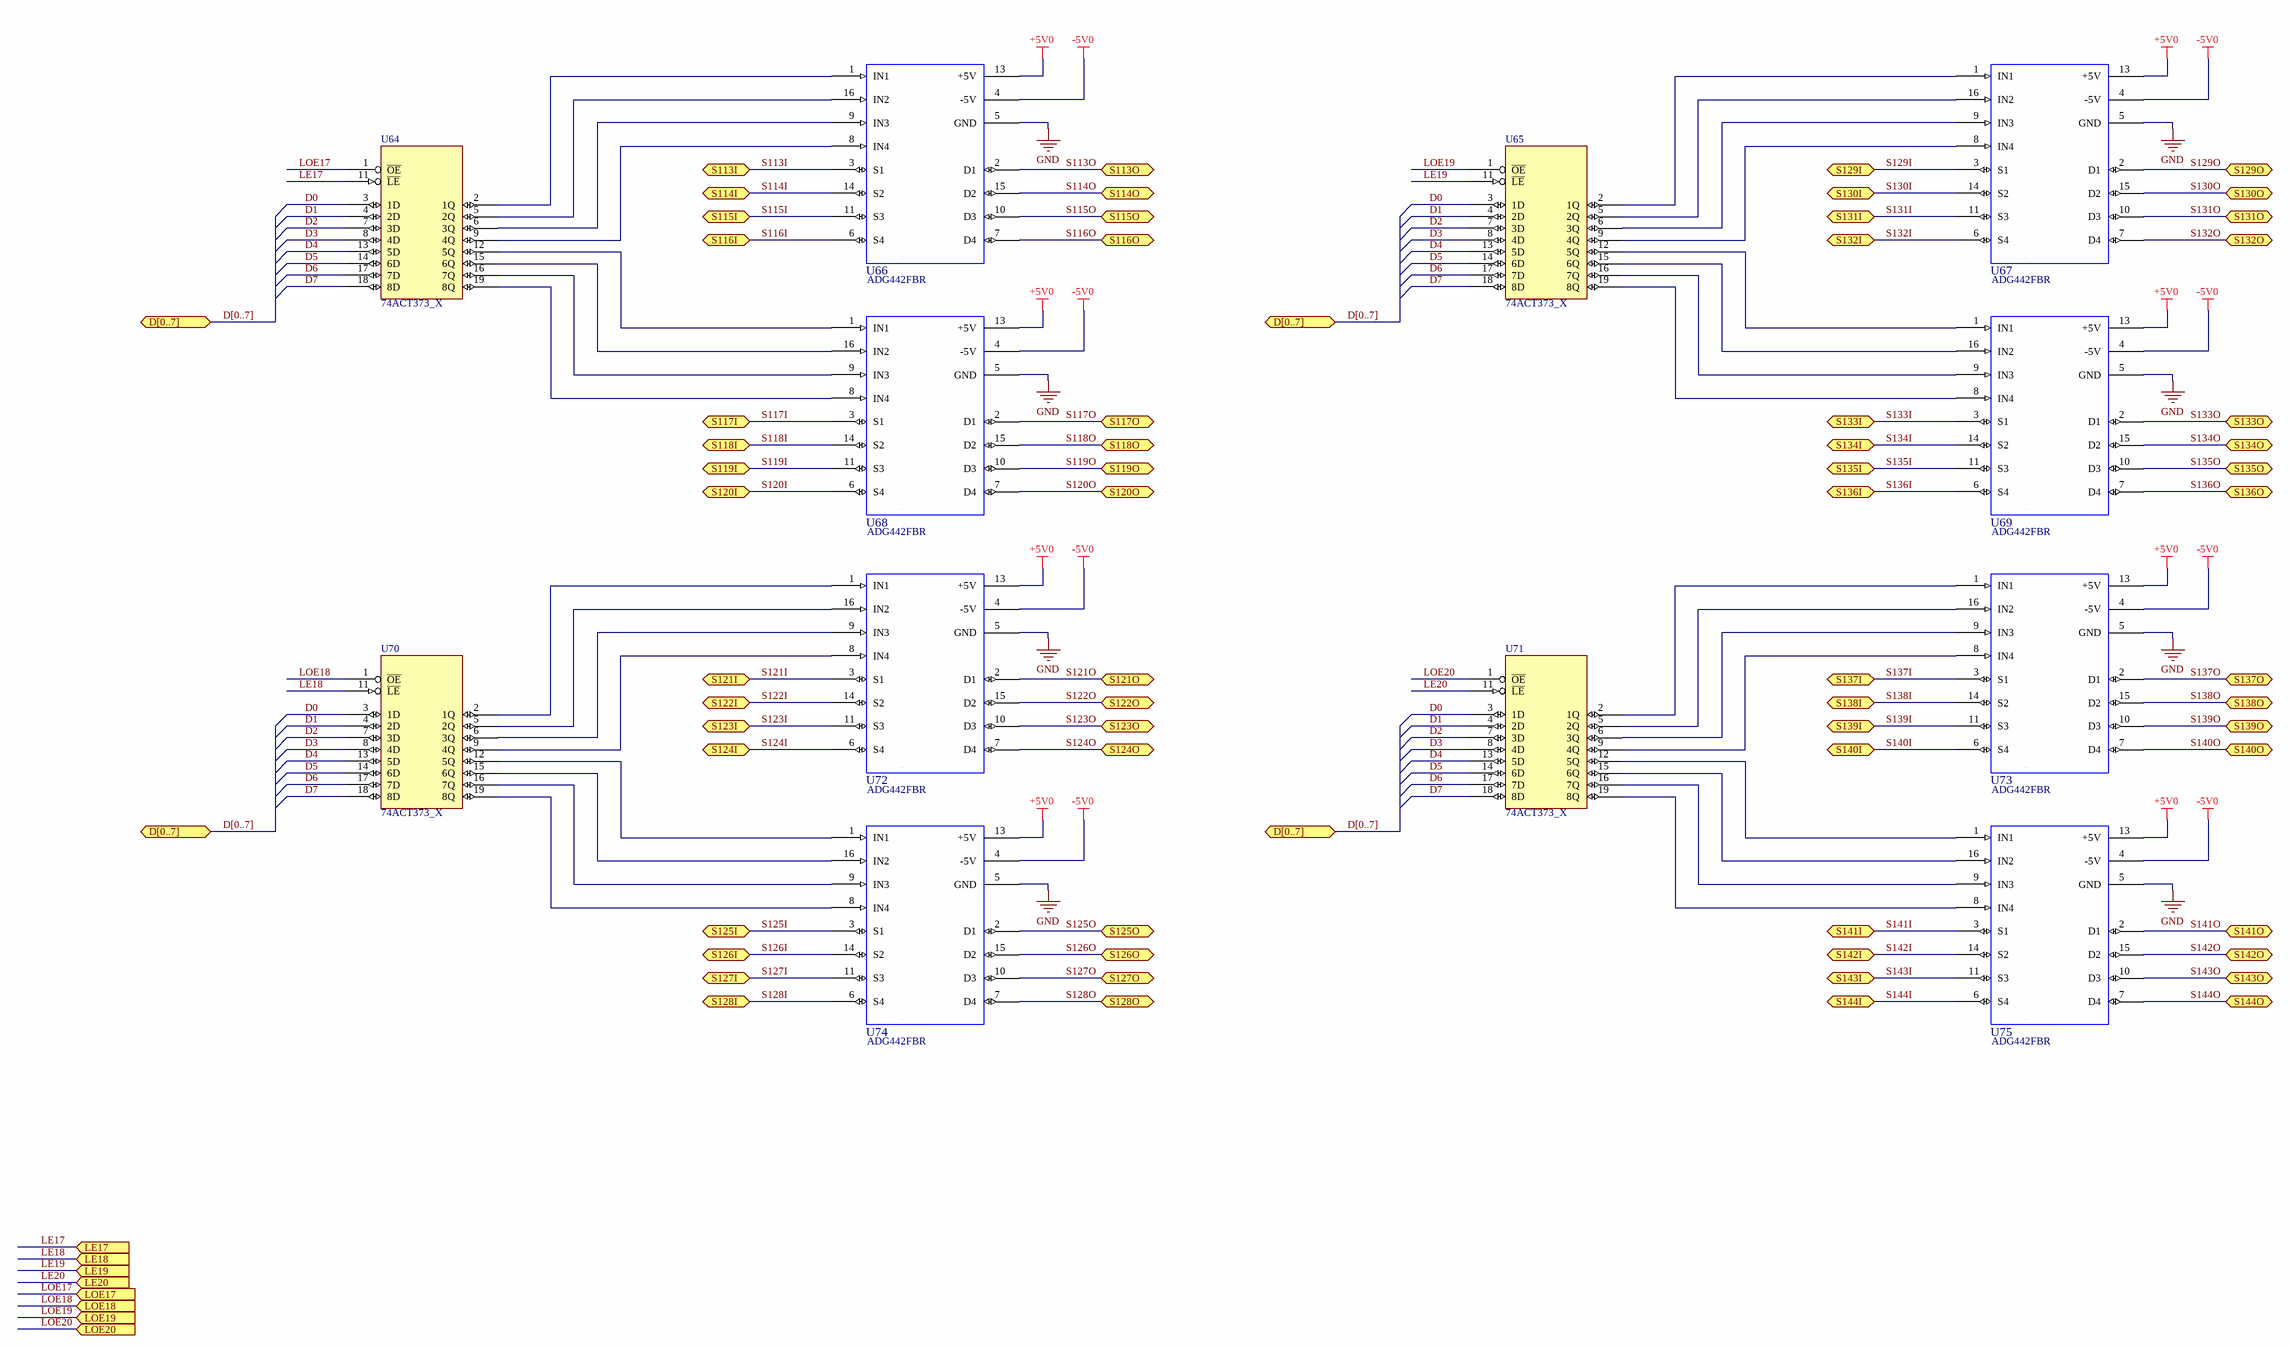
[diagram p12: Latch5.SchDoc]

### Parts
U64  74ACT373_X  [SOL-20/N]
U65  74ACT373_X  [SOL-20/N]
U66  VENDOR PART NO: ADG442FBR  [SO-16/N]  (hidden comment: ADG442)
U67  VENDOR PART NO: ADG442FBR  [SO-16/N]  (hidden comment: ADG442)
U68  VENDOR PART NO: ADG442FBR  [SO-16/N]  (hidden comment: ADG442)
U69  VENDOR PART NO: ADG442FBR  [SO-16/N]  (hidden comment: ADG442)
U70  74ACT373_X  [SOL-20/N]
U71  74ACT373_X  [SOL-20/N]
U72  VENDOR PART NO: ADG442FBR  [SO-16/N]  (hidden comment: ADG442)
U73  VENDOR PART NO: ADG442FBR  [SO-16/N]  (hidden comment: ADG442)
U74  VENDOR PART NO: ADG442FBR  [SO-16/N]  (hidden comment: ADG442)
U75  VENDOR PART NO: ADG442FBR  [SO-16/N]  (hidden comment: ADG442)

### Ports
D[0..7] (bidir), LE17 (in), LE18 (in), LE19 (in), LE20 (in), LOE17 (in), LOE18 (in), LOE19 (in), LOE20 (in), S113I (bidir), S113O (bidir), S114I (bidir), S114O (bidir), S115I (bidir), S115O (bidir), S116I (bidir), S116O (bidir), S117I (bidir), S117O (bidir), S118I (bidir), S118O (bidir), S119I (bidir), S119O (bidir), S120I (bidir), S120O (bidir), S121I (bidir), S121O (bidir), S122I (bidir), S122O (bidir), S123I (bidir), S123O (bidir), S124I (bidir), S124O (bidir), S125I (bidir), S125O (bidir), S126I (bidir), S126O (bidir), S127I (bidir), S127O (bidir), S128I (bidir), S128O (bidir), S129I (bidir), S129O (bidir), S130I (bidir), S130O (bidir), S131I (bidir), S131O (bidir), S132I (bidir), S132O (bidir), S133I (bidir), S133O (bidir), S134I (bidir), S134O (bidir), S135I (bidir), S135O (bidir), S136I (bidir), S136O (bidir), S137I (bidir), S137O (bidir), S138I (bidir), S138O (bidir), S139I (bidir), S139O (bidir), S140I (bidir), S140O (bidir), S141I (bidir), S141O (bidir), S142I (bidir), S142O (bidir), S143I (bidir), S143O (bidir), S144I (bidir), S144O (bidir)

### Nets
+5V0: U66.13(+5V) U67.13(+5V) U68.13(+5V) U69.13(+5V) U72.13(+5V) U73.13(+5V) U74.13(+5V) U75.13(+5V)
-5V0: U66.4(-5V) U67.4(-5V) U68.4(-5V) U69.4(-5V) U72.4(-5V) U73.4(-5V) U74.4(-5V) U75.4(-5V)
GND: U66.5(GND) U67.5(GND) U68.5(GND) U69.5(GND) U72.5(GND) U73.5(GND) U74.5(GND) U75.5(GND)
D0: U64.3(1D) U65.3(1D) U70.3(1D) U71.3(1D)
D1: U64.4(2D) U65.4(2D) U70.4(2D) U71.4(2D)
D2: U64.7(3D) U65.7(3D) U70.7(3D) U71.7(3D)
D3: U64.8(4D) U65.8(4D) U70.8(4D) U71.8(4D)
D4: U64.13(5D) U65.13(5D) U70.13(5D) U71.13(5D)
D5: U64.14(6D) U65.14(6D) U70.14(6D) U71.14(6D)
D6: U64.17(7D) U65.17(7D) U70.17(7D) U71.17(7D)
D7: U64.18(8D) U65.18(8D) U70.18(8D) U71.18(8D)
LE17: U64.11(~{LE}) ; port LE17
LE18: U70.11(~{LE}) ; port LE18
LE19: U65.11(~{LE}) ; port LE19
LE20: U71.11(~{LE}) ; port LE20
LOE17: U64.1(~{OE}) ; port LOE17
LOE18: U70.1(~{OE}) ; port LOE18
LOE19: U65.1(~{OE}) ; port LOE19
LOE20: U71.1(~{OE}) ; port LOE20
S113I: U66.3(S1) ; port S113I
S113O: U66.2(D1) ; port S113O
S114I: U66.14(S2) ; port S114I
S114O: U66.15(D2) ; port S114O
S115I: U66.11(S3) ; port S115I
S115O: U66.10(D3) ; port S115O
S116I: U66.6(S4) ; port S116I
S116O: U66.7(D4) ; port S116O
S117I: U68.3(S1) ; port S117I
S117O: U68.2(D1) ; port S117O
S118I: U68.14(S2) ; port S118I
S118O: U68.15(D2) ; port S118O
S119I: U68.11(S3) ; port S119I
S119O: U68.10(D3) ; port S119O
S120I: U68.6(S4) ; port S120I
S120O: U68.7(D4) ; port S120O
S121I: U72.3(S1) ; port S121I
S121O: U72.2(D1) ; port S121O
S122I: U72.14(S2) ; port S122I
S122O: U72.15(D2) ; port S122O
S123I: U72.11(S3) ; port S123I
S123O: U72.10(D3) ; port S123O
S124I: U72.6(S4) ; port S124I
S124O: U72.7(D4) ; port S124O
S125I: U74.3(S1) ; port S125I
S125O: U74.2(D1) ; port S125O
S126I: U74.14(S2) ; port S126I
S126O: U74.15(D2) ; port S126O
S127I: U74.11(S3) ; port S127I
S127O: U74.10(D3) ; port S127O
S128I: U74.6(S4) ; port S128I
S128O: U74.7(D4) ; port S128O
S129I: U67.3(S1) ; port S129I
S129O: U67.2(D1) ; port S129O
S130I: U67.14(S2) ; port S130I
S130O: U67.15(D2) ; port S130O
S131I: U67.11(S3) ; port S131I
S131O: U67.10(D3) ; port S131O
S132I: U67.6(S4) ; port S132I
S132O: U67.7(D4) ; port S132O
S133I: U69.3(S1) ; port S133I
S133O: U69.2(D1) ; port S133O
S134I: U69.14(S2) ; port S134I
S134O: U69.15(D2) ; port S134O
S135I: U69.11(S3) ; port S135I
S135O: U69.10(D3) ; port S135O
S136I: U69.6(S4) ; port S136I
S136O: U69.7(D4) ; port S136O
S137I: U73.3(S1) ; port S137I
S137O: U73.2(D1) ; port S137O
S138I: U73.14(S2) ; port S138I
S138O: U73.15(D2) ; port S138O
S139I: U73.11(S3) ; port S139I
S139O: U73.10(D3) ; port S139O
S140I: U73.6(S4) ; port S140I
S140O: U73.7(D4) ; port S140O
S141I: U75.3(S1) ; port S141I
S141O: U75.2(D1) ; port S141O
S142I: U75.14(S2) ; port S142I
S142O: U75.15(D2) ; port S142O
S143I: U75.11(S3) ; port S143I
S143O: U75.10(D3) ; port S143O
S144I: U75.6(S4) ; port S144I
S144O: U75.7(D4) ; port S144O
NetU64_2: U64.2(1Q) U66.1(IN1)
NetU64_5: U64.5(2Q) U66.16(IN2)
NetU64_6: U64.6(3Q) U66.9(IN3)
NetU64_9: U64.9(4Q) U66.8(IN4)
NetU64_12: U64.12(5Q) U68.1(IN1)
NetU64_15: U64.15(6Q) U68.16(IN2)
NetU64_16: U64.16(7Q) U68.9(IN3)
NetU64_19: U64.19(8Q) U68.8(IN4)
NetU65_2: U65.2(1Q) U67.1(IN1)
NetU65_5: U65.5(2Q) U67.16(IN2)
NetU65_6: U65.6(3Q) U67.9(IN3)
NetU65_9: U65.9(4Q) U67.8(IN4)
NetU65_12: U65.12(5Q) U69.1(IN1)
NetU65_15: U65.15(6Q) U69.16(IN2)
NetU65_16: U65.16(7Q) U69.9(IN3)
NetU65_19: U65.19(8Q) U69.8(IN4)
NetU70_2: U70.2(1Q) U72.1(IN1)
NetU70_5: U70.5(2Q) U72.16(IN2)
NetU70_6: U70.6(3Q) U72.9(IN3)
NetU70_9: U70.9(4Q) U72.8(IN4)
NetU70_12: U70.12(5Q) U74.1(IN1)
NetU70_15: U70.15(6Q) U74.16(IN2)
NetU70_16: U70.16(7Q) U74.9(IN3)
NetU70_19: U70.19(8Q) U74.8(IN4)
NetU71_2: U71.2(1Q) U73.1(IN1)
NetU71_5: U71.5(2Q) U73.16(IN2)
NetU71_6: U71.6(3Q) U73.9(IN3)
NetU71_9: U71.9(4Q) U73.8(IN4)
NetU71_12: U71.12(5Q) U75.1(IN1)
NetU71_15: U71.15(6Q) U75.16(IN2)
NetU71_16: U71.16(7Q) U75.9(IN3)
NetU71_19: U71.19(8Q) U75.8(IN4)

Not connected (* = marked no-connect by the designer): U64 10(GND) 20(VCC); U65 10(GND) 20(VCC); U70 10(GND) 20(VCC); U71 10(GND) 20(VCC)

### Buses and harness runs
bus D[0..7] = port D[0..7]

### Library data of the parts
U64 U65 U70 U71 = 74ACT373_X: as U16 on sheet Latch1
U66-U69 U72-U75 = ADG439FBR_X: as U18 on sheet Latch1

## Sheet Latch6.SchDoc: P.C. BOARD
size A2; Revision: A; SheetNumber: 0; SheetTotal: 0
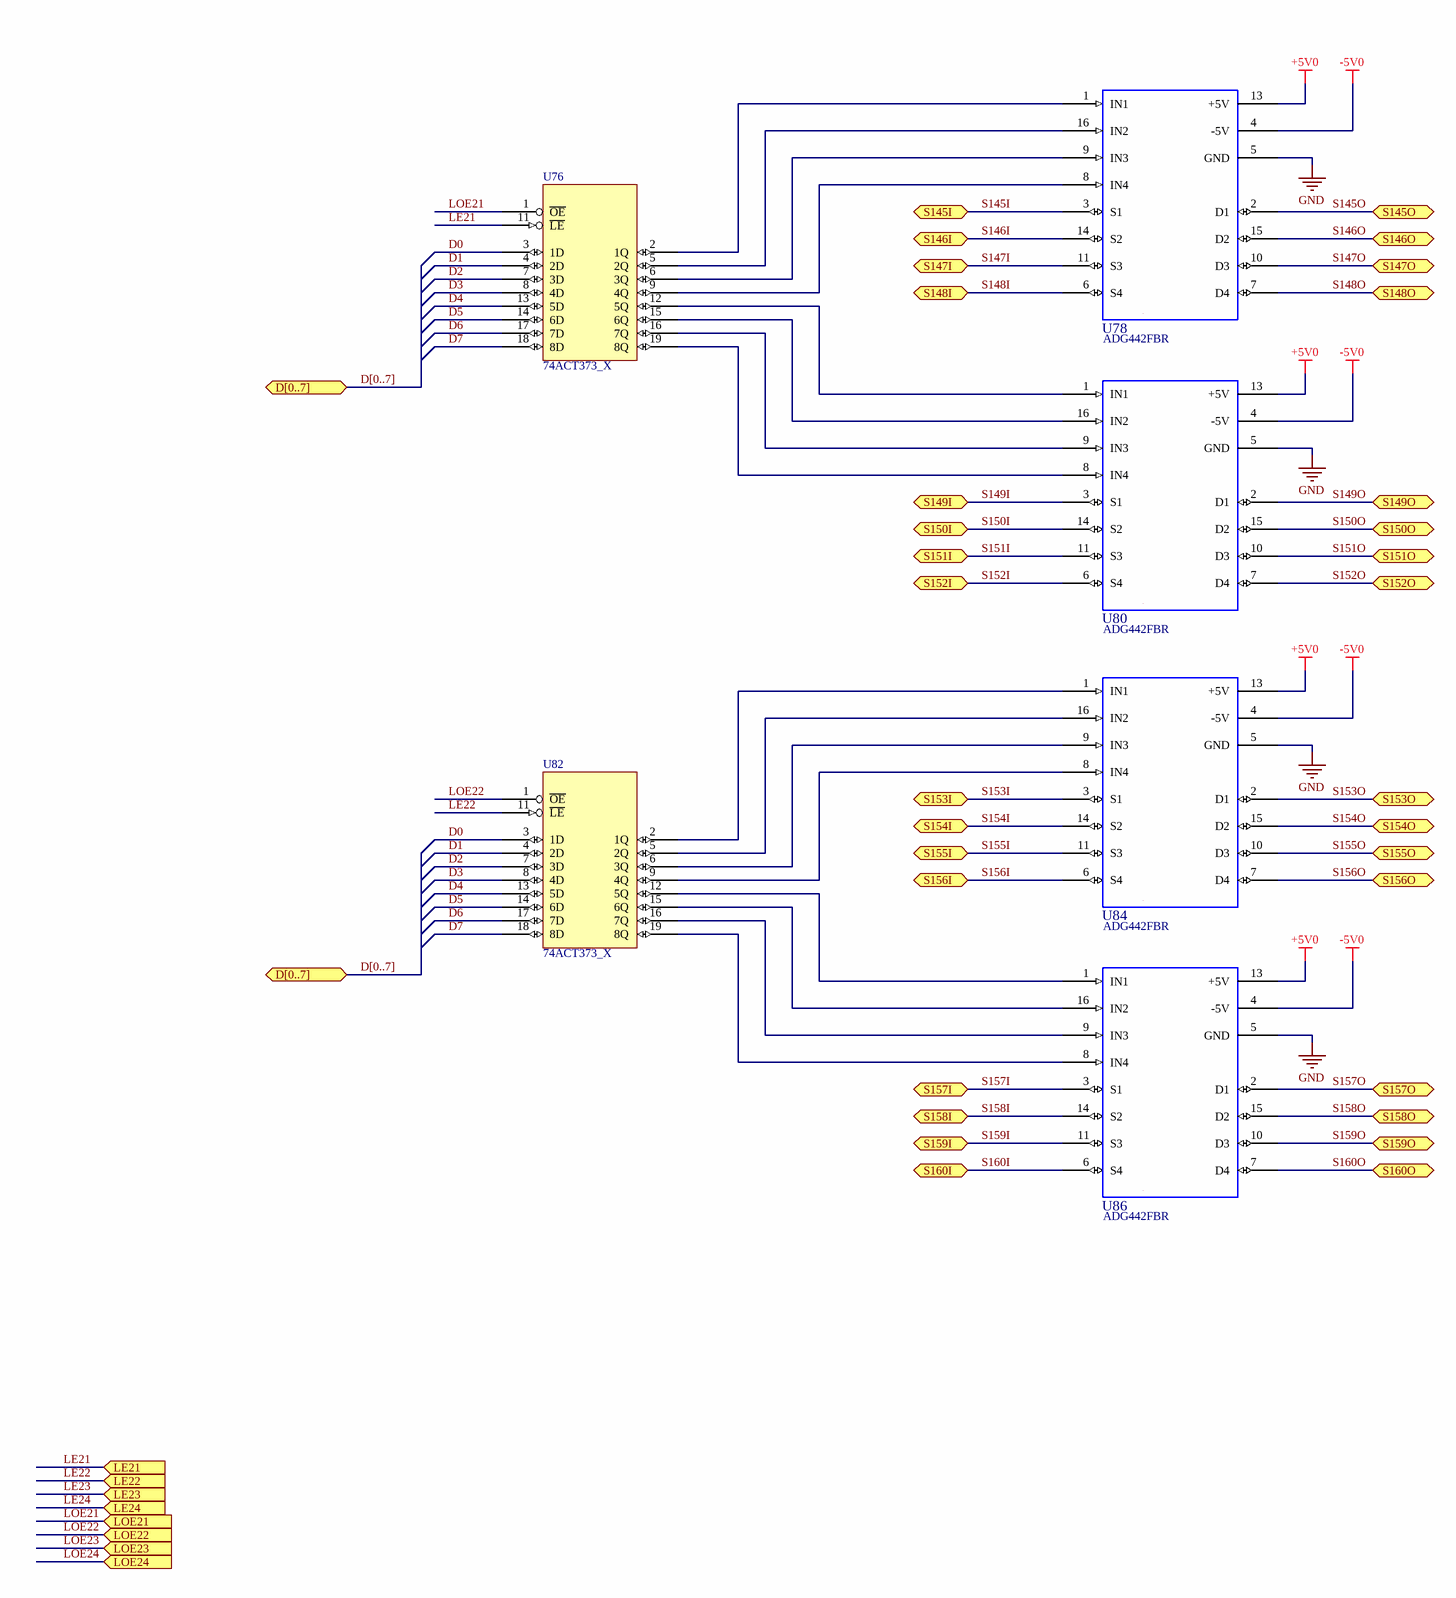
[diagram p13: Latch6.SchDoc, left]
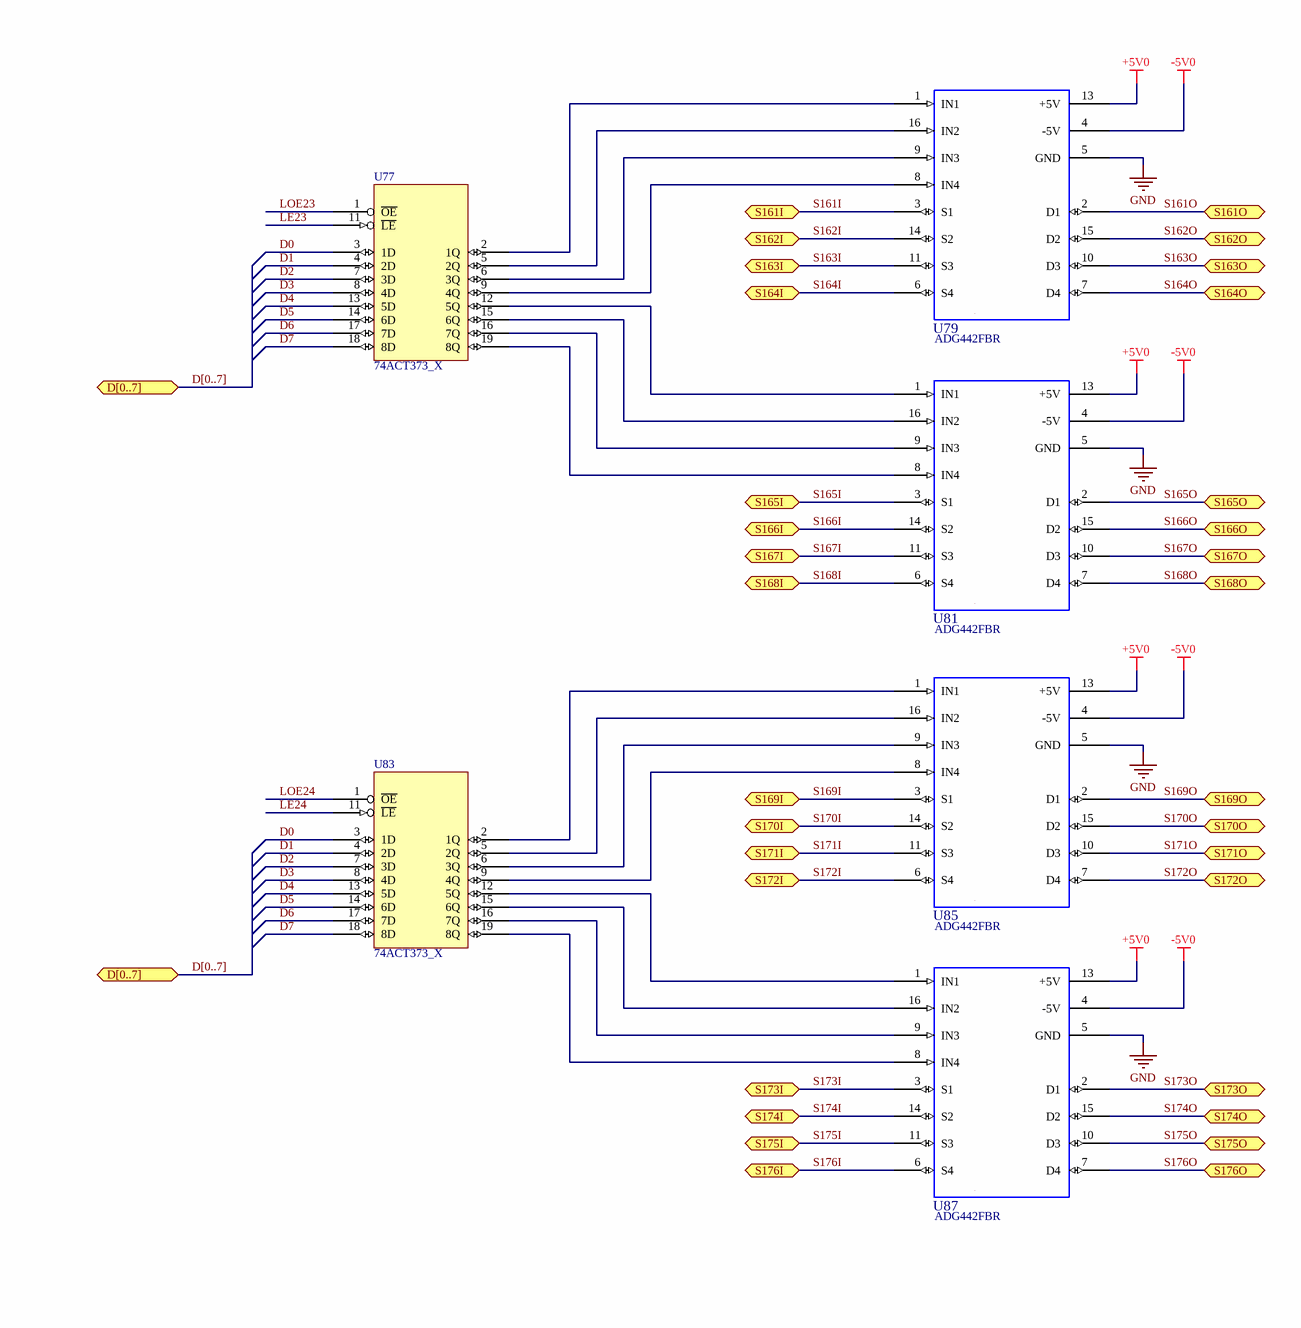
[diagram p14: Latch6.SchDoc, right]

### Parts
U76  74ACT373_X  [SOL-20/N]
U77  74ACT373_X  [SOL-20/N]
U78  VENDOR PART NO: ADG442FBR  [SO-16/N]  (hidden comment: ADG442)
U79  VENDOR PART NO: ADG442FBR  [SO-16/N]  (hidden comment: ADG442)
U80  VENDOR PART NO: ADG442FBR  [SO-16/N]  (hidden comment: ADG442)
U81  VENDOR PART NO: ADG442FBR  [SO-16/N]  (hidden comment: ADG442)
U82  74ACT373_X  [SOL-20/N]
U83  74ACT373_X  [SOL-20/N]
U84  VENDOR PART NO: ADG442FBR  [SO-16/N]  (hidden comment: ADG442)
U85  VENDOR PART NO: ADG442FBR  [SO-16/N]  (hidden comment: ADG442)
U86  VENDOR PART NO: ADG442FBR  [SO-16/N]  (hidden comment: ADG442)
U87  VENDOR PART NO: ADG442FBR  [SO-16/N]  (hidden comment: ADG442)

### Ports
D[0..7] (bidir), LE21 (in), LE22 (in), LE23 (in), LE24 (in), LOE21 (in), LOE22 (in), LOE23 (in), LOE24 (in), S145I (bidir), S145O (bidir), S146I (bidir), S146O (bidir), S147I (bidir), S147O (bidir), S148I (bidir), S148O (bidir), S149I (bidir), S149O (bidir), S150I (bidir), S150O (bidir), S151I (bidir), S151O (bidir), S152I (bidir), S152O (bidir), S153I (bidir), S153O (bidir), S154I (bidir), S154O (bidir), S155I (bidir), S155O (bidir), S156I (bidir), S156O (bidir), S157I (bidir), S157O (bidir), S158I (bidir), S158O (bidir), S159I (bidir), S159O (bidir), S160I (bidir), S160O (bidir), S161I (bidir), S161O (bidir), S162I (bidir), S162O (bidir), S163I (bidir), S163O (bidir), S164I (bidir), S164O (bidir), S165I (bidir), S165O (bidir), S166I (bidir), S166O (bidir), S167I (bidir), S167O (bidir), S168I (bidir), S168O (bidir), S169I (bidir), S169O (bidir), S170I (bidir), S170O (bidir), S171I (bidir), S171O (bidir), S172I (bidir), S172O (bidir), S173I (bidir), S173O (bidir), S174I (bidir), S174O (bidir), S175I (bidir), S175O (bidir), S176I (bidir), S176O (bidir)

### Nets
+5V0: U78.13(+5V) U79.13(+5V) U80.13(+5V) U81.13(+5V) U84.13(+5V) U85.13(+5V) U86.13(+5V) U87.13(+5V)
-5V0: U78.4(-5V) U79.4(-5V) U80.4(-5V) U81.4(-5V) U84.4(-5V) U85.4(-5V) U86.4(-5V) U87.4(-5V)
GND: U78.5(GND) U79.5(GND) U80.5(GND) U81.5(GND) U84.5(GND) U85.5(GND) U86.5(GND) U87.5(GND)
D0: U76.3(1D) U77.3(1D) U82.3(1D) U83.3(1D)
D1: U76.4(2D) U77.4(2D) U82.4(2D) U83.4(2D)
D2: U76.7(3D) U77.7(3D) U82.7(3D) U83.7(3D)
D3: U76.8(4D) U77.8(4D) U82.8(4D) U83.8(4D)
D4: U76.13(5D) U77.13(5D) U82.13(5D) U83.13(5D)
D5: U76.14(6D) U77.14(6D) U82.14(6D) U83.14(6D)
D6: U76.17(7D) U77.17(7D) U82.17(7D) U83.17(7D)
D7: U76.18(8D) U77.18(8D) U82.18(8D) U83.18(8D)
LE21: U76.11(~{LE}) ; port LE21
LE22: U82.11(~{LE}) ; port LE22
LE23: U77.11(~{LE}) ; port LE23
LE24: U83.11(~{LE}) ; port LE24
LOE21: U76.1(~{OE}) ; port LOE21
LOE22: U82.1(~{OE}) ; port LOE22
LOE23: U77.1(~{OE}) ; port LOE23
LOE24: U83.1(~{OE}) ; port LOE24
S145I: U78.3(S1) ; port S145I
S145O: U78.2(D1) ; port S145O
S146I: U78.14(S2) ; port S146I
S146O: U78.15(D2) ; port S146O
S147I: U78.11(S3) ; port S147I
S147O: U78.10(D3) ; port S147O
S148I: U78.6(S4) ; port S148I
S148O: U78.7(D4) ; port S148O
S149I: U80.3(S1) ; port S149I
S149O: U80.2(D1) ; port S149O
S150I: U80.14(S2) ; port S150I
S150O: U80.15(D2) ; port S150O
S151I: U80.11(S3) ; port S151I
S151O: U80.10(D3) ; port S151O
S152I: U80.6(S4) ; port S152I
S152O: U80.7(D4) ; port S152O
S153I: U84.3(S1) ; port S153I
S153O: U84.2(D1) ; port S153O
S154I: U84.14(S2) ; port S154I
S154O: U84.15(D2) ; port S154O
S155I: U84.11(S3) ; port S155I
S155O: U84.10(D3) ; port S155O
S156I: U84.6(S4) ; port S156I
S156O: U84.7(D4) ; port S156O
S157I: U86.3(S1) ; port S157I
S157O: U86.2(D1) ; port S157O
S158I: U86.14(S2) ; port S158I
S158O: U86.15(D2) ; port S158O
S159I: U86.11(S3) ; port S159I
S159O: U86.10(D3) ; port S159O
S160I: U86.6(S4) ; port S160I
S160O: U86.7(D4) ; port S160O
S161I: U79.3(S1) ; port S161I
S161O: U79.2(D1) ; port S161O
S162I: U79.14(S2) ; port S162I
S162O: U79.15(D2) ; port S162O
S163I: U79.11(S3) ; port S163I
S163O: U79.10(D3) ; port S163O
S164I: U79.6(S4) ; port S164I
S164O: U79.7(D4) ; port S164O
S165I: U81.3(S1) ; port S165I
S165O: U81.2(D1) ; port S165O
S166I: U81.14(S2) ; port S166I
S166O: U81.15(D2) ; port S166O
S167I: U81.11(S3) ; port S167I
S167O: U81.10(D3) ; port S167O
S168I: U81.6(S4) ; port S168I
S168O: U81.7(D4) ; port S168O
S169I: U85.3(S1) ; port S169I
S169O: U85.2(D1) ; port S169O
S170I: U85.14(S2) ; port S170I
S170O: U85.15(D2) ; port S170O
S171I: U85.11(S3) ; port S171I
S171O: U85.10(D3) ; port S171O
S172I: U85.6(S4) ; port S172I
S172O: U85.7(D4) ; port S172O
S173I: U87.3(S1) ; port S173I
S173O: U87.2(D1) ; port S173O
S174I: U87.14(S2) ; port S174I
S174O: U87.15(D2) ; port S174O
S175I: U87.11(S3) ; port S175I
S175O: U87.10(D3) ; port S175O
S176I: U87.6(S4) ; port S176I
S176O: U87.7(D4) ; port S176O
NetU76_2: U76.2(1Q) U78.1(IN1)
NetU76_5: U76.5(2Q) U78.16(IN2)
NetU76_6: U76.6(3Q) U78.9(IN3)
NetU76_9: U76.9(4Q) U78.8(IN4)
NetU76_12: U76.12(5Q) U80.1(IN1)
NetU76_15: U76.15(6Q) U80.16(IN2)
NetU76_16: U76.16(7Q) U80.9(IN3)
NetU76_19: U76.19(8Q) U80.8(IN4)
NetU77_2: U77.2(1Q) U79.1(IN1)
NetU77_5: U77.5(2Q) U79.16(IN2)
NetU77_6: U77.6(3Q) U79.9(IN3)
NetU77_9: U77.9(4Q) U79.8(IN4)
NetU77_12: U77.12(5Q) U81.1(IN1)
NetU77_15: U77.15(6Q) U81.16(IN2)
NetU77_16: U77.16(7Q) U81.9(IN3)
NetU77_19: U77.19(8Q) U81.8(IN4)
NetU82_2: U82.2(1Q) U84.1(IN1)
NetU82_5: U82.5(2Q) U84.16(IN2)
NetU82_6: U82.6(3Q) U84.9(IN3)
NetU82_9: U82.9(4Q) U84.8(IN4)
NetU82_12: U82.12(5Q) U86.1(IN1)
NetU82_15: U82.15(6Q) U86.16(IN2)
NetU82_16: U82.16(7Q) U86.9(IN3)
NetU82_19: U82.19(8Q) U86.8(IN4)
NetU83_2: U83.2(1Q) U85.1(IN1)
NetU83_5: U83.5(2Q) U85.16(IN2)
NetU83_6: U83.6(3Q) U85.9(IN3)
NetU83_9: U83.9(4Q) U85.8(IN4)
NetU83_12: U83.12(5Q) U87.1(IN1)
NetU83_15: U83.15(6Q) U87.16(IN2)
NetU83_16: U83.16(7Q) U87.9(IN3)
NetU83_19: U83.19(8Q) U87.8(IN4)

Not connected (* = marked no-connect by the designer): U76 10(GND) 20(VCC); U77 10(GND) 20(VCC); U82 10(GND) 20(VCC); U83 10(GND) 20(VCC)

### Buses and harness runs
bus D[0..7] = port D[0..7]

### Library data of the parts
U76 U77 U82 U83 = 74ACT373_X: as U16 on sheet Latch1
U78-U81 U84-U87 = ADG439FBR_X: as U18 on sheet Latch1

## Sheet Latch7.SchDoc: P.C. BOARD
size A2; Revision: A; SheetNumber: 0; SheetTotal: 0
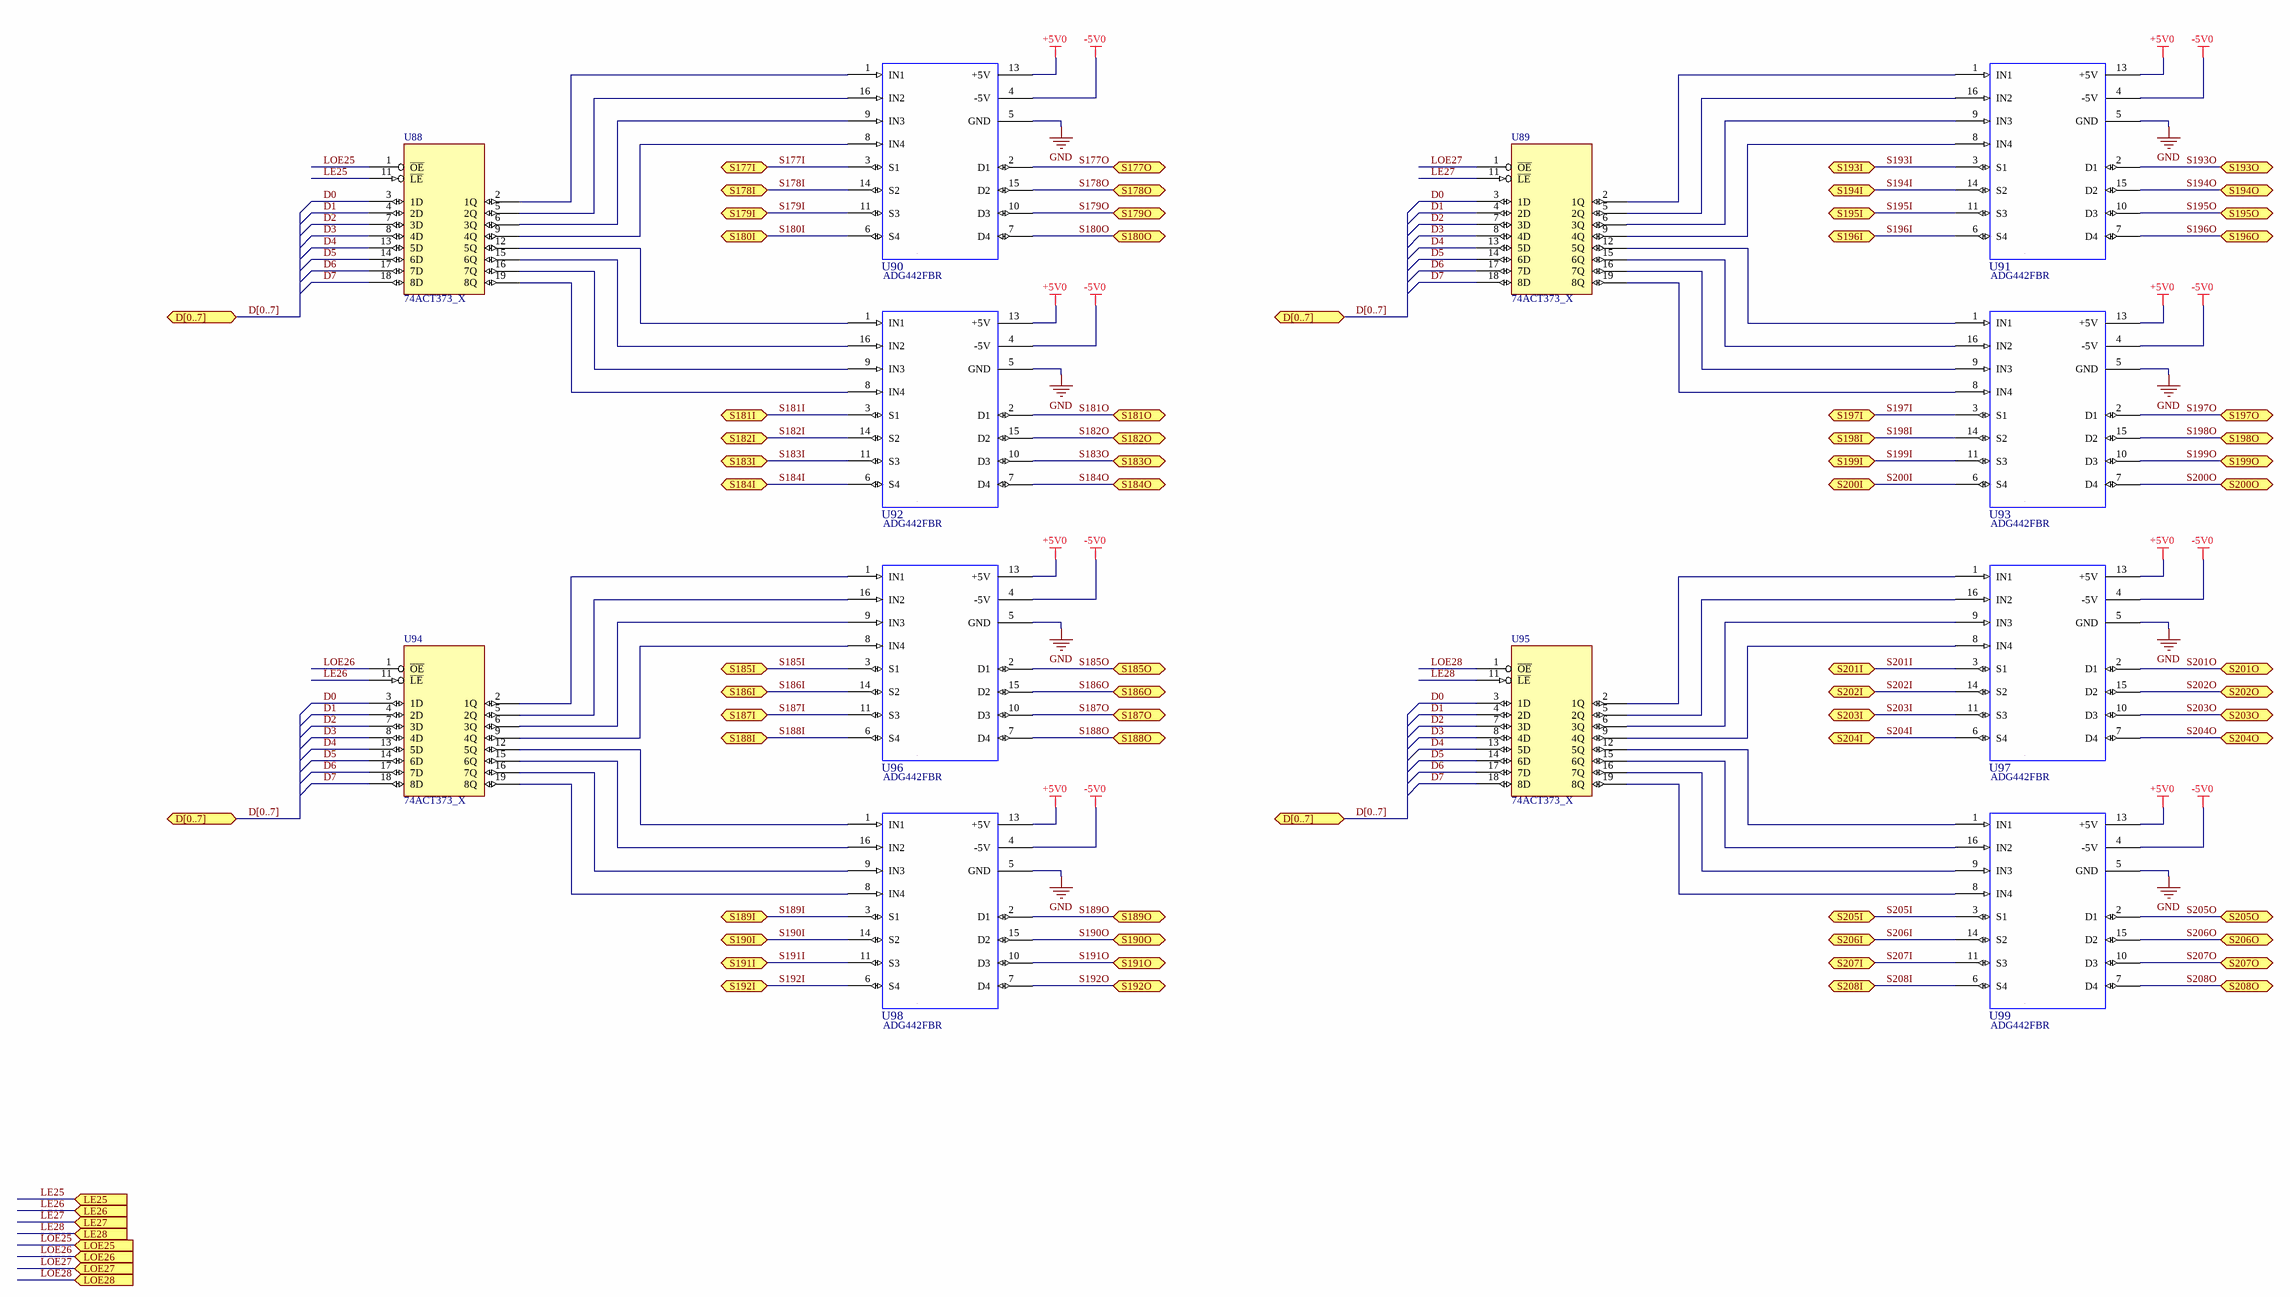
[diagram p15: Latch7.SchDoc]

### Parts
U88  74ACT373_X  [SOL-20/N]
U89  74ACT373_X  [SOL-20/N]
U90  VENDOR PART NO: ADG442FBR  [SO-16/N]  (hidden comment: ADG442)
U91  VENDOR PART NO: ADG442FBR  [SO-16/N]  (hidden comment: ADG442)
U92  VENDOR PART NO: ADG442FBR  [SO-16/N]  (hidden comment: ADG442)
U93  VENDOR PART NO: ADG442FBR  [SO-16/N]  (hidden comment: ADG442)
U94  74ACT373_X  [SOL-20/N]
U95  74ACT373_X  [SOL-20/N]
U96  VENDOR PART NO: ADG442FBR  [SO-16/N]  (hidden comment: ADG442)
U97  VENDOR PART NO: ADG442FBR  [SO-16/N]  (hidden comment: ADG442)
U98  VENDOR PART NO: ADG442FBR  [SO-16/N]  (hidden comment: ADG442)
U99  VENDOR PART NO: ADG442FBR  [SO-16/N]  (hidden comment: ADG442)

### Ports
D[0..7] (bidir), LE25 (in), LE26 (in), LE27 (in), LE28 (in), LOE25 (in), LOE26 (in), LOE27 (in), LOE28 (in), S177I (bidir), S177O (bidir), S178I (bidir), S178O (bidir), S179I (bidir), S179O (bidir), S180I (bidir), S180O (bidir), S181I (bidir), S181O (bidir), S182I (bidir), S182O (bidir), S183I (bidir), S183O (bidir), S184I (bidir), S184O (bidir), S185I (bidir), S185O (bidir), S186I (bidir), S186O (bidir), S187I (bidir), S187O (bidir), S188I (bidir), S188O (bidir), S189I (bidir), S189O (bidir), S190I (bidir), S190O (bidir), S191I (bidir), S191O (bidir), S192I (bidir), S192O (bidir), S193I (bidir), S193O (bidir), S194I (bidir), S194O (bidir), S195I (bidir), S195O (bidir), S196I (bidir), S196O (bidir), S197I (bidir), S197O (bidir), S198I (bidir), S198O (bidir), S199I (bidir), S199O (bidir), S200I (bidir), S200O (bidir), S201I (bidir), S201O (bidir), S202I (bidir), S202O (bidir), S203I (bidir), S203O (bidir), S204I (bidir), S204O (bidir), S205I (bidir), S205O (bidir), S206I (bidir), S206O (bidir), S207I (bidir), S207O (bidir), S208I (bidir), S208O (bidir)

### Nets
+5V0: U90.13(+5V) U91.13(+5V) U92.13(+5V) U93.13(+5V) U96.13(+5V) U97.13(+5V) U98.13(+5V) U99.13(+5V)
-5V0: U90.4(-5V) U91.4(-5V) U92.4(-5V) U93.4(-5V) U96.4(-5V) U97.4(-5V) U98.4(-5V) U99.4(-5V)
GND: U90.5(GND) U91.5(GND) U92.5(GND) U93.5(GND) U96.5(GND) U97.5(GND) U98.5(GND) U99.5(GND)
D0: U88.3(1D) U89.3(1D) U94.3(1D) U95.3(1D)
D1: U88.4(2D) U89.4(2D) U94.4(2D) U95.4(2D)
D2: U88.7(3D) U89.7(3D) U94.7(3D) U95.7(3D)
D3: U88.8(4D) U89.8(4D) U94.8(4D) U95.8(4D)
D4: U88.13(5D) U89.13(5D) U94.13(5D) U95.13(5D)
D5: U88.14(6D) U89.14(6D) U94.14(6D) U95.14(6D)
D6: U88.17(7D) U89.17(7D) U94.17(7D) U95.17(7D)
D7: U88.18(8D) U89.18(8D) U94.18(8D) U95.18(8D)
LE25: U88.11(~{LE}) ; port LE25
LE26: U94.11(~{LE}) ; port LE26
LE27: U89.11(~{LE}) ; port LE27
LE28: U95.11(~{LE}) ; port LE28
LOE25: U88.1(~{OE}) ; port LOE25
LOE26: U94.1(~{OE}) ; port LOE26
LOE27: U89.1(~{OE}) ; port LOE27
LOE28: U95.1(~{OE}) ; port LOE28
S177I: U90.3(S1) ; port S177I
S177O: U90.2(D1) ; port S177O
S178I: U90.14(S2) ; port S178I
S178O: U90.15(D2) ; port S178O
S179I: U90.11(S3) ; port S179I
S179O: U90.10(D3) ; port S179O
S180I: U90.6(S4) ; port S180I
S180O: U90.7(D4) ; port S180O
S181I: U92.3(S1) ; port S181I
S181O: U92.2(D1) ; port S181O
S182I: U92.14(S2) ; port S182I
S182O: U92.15(D2) ; port S182O
S183I: U92.11(S3) ; port S183I
S183O: U92.10(D3) ; port S183O
S184I: U92.6(S4) ; port S184I
S184O: U92.7(D4) ; port S184O
S185I: U96.3(S1) ; port S185I
S185O: U96.2(D1) ; port S185O
S186I: U96.14(S2) ; port S186I
S186O: U96.15(D2) ; port S186O
S187I: U96.11(S3) ; port S187I
S187O: U96.10(D3) ; port S187O
S188I: U96.6(S4) ; port S188I
S188O: U96.7(D4) ; port S188O
S189I: U98.3(S1) ; port S189I
S189O: U98.2(D1) ; port S189O
S190I: U98.14(S2) ; port S190I
S190O: U98.15(D2) ; port S190O
S191I: U98.11(S3) ; port S191I
S191O: U98.10(D3) ; port S191O
S192I: U98.6(S4) ; port S192I
S192O: U98.7(D4) ; port S192O
S193I: U91.3(S1) ; port S193I
S193O: U91.2(D1) ; port S193O
S194I: U91.14(S2) ; port S194I
S194O: U91.15(D2) ; port S194O
S195I: U91.11(S3) ; port S195I
S195O: U91.10(D3) ; port S195O
S196I: U91.6(S4) ; port S196I
S196O: U91.7(D4) ; port S196O
S197I: U93.3(S1) ; port S197I
S197O: U93.2(D1) ; port S197O
S198I: U93.14(S2) ; port S198I
S198O: U93.15(D2) ; port S198O
S199I: U93.11(S3) ; port S199I
S199O: U93.10(D3) ; port S199O
S200I: U93.6(S4) ; port S200I
S200O: U93.7(D4) ; port S200O
S201I: U97.3(S1) ; port S201I
S201O: U97.2(D1) ; port S201O
S202I: U97.14(S2) ; port S202I
S202O: U97.15(D2) ; port S202O
S203I: U97.11(S3) ; port S203I
S203O: U97.10(D3) ; port S203O
S204I: U97.6(S4) ; port S204I
S204O: U97.7(D4) ; port S204O
S205I: U99.3(S1) ; port S205I
S205O: U99.2(D1) ; port S205O
S206I: U99.14(S2) ; port S206I
S206O: U99.15(D2) ; port S206O
S207I: U99.11(S3) ; port S207I
S207O: U99.10(D3) ; port S207O
S208I: U99.6(S4) ; port S208I
S208O: U99.7(D4) ; port S208O
NetU88_2: U88.2(1Q) U90.1(IN1)
NetU88_5: U88.5(2Q) U90.16(IN2)
NetU88_6: U88.6(3Q) U90.9(IN3)
NetU88_9: U88.9(4Q) U90.8(IN4)
NetU88_12: U88.12(5Q) U92.1(IN1)
NetU88_15: U88.15(6Q) U92.16(IN2)
NetU88_16: U88.16(7Q) U92.9(IN3)
NetU88_19: U88.19(8Q) U92.8(IN4)
NetU89_2: U89.2(1Q) U91.1(IN1)
NetU89_5: U89.5(2Q) U91.16(IN2)
NetU89_6: U89.6(3Q) U91.9(IN3)
NetU89_9: U89.9(4Q) U91.8(IN4)
NetU89_12: U89.12(5Q) U93.1(IN1)
NetU89_15: U89.15(6Q) U93.16(IN2)
NetU89_16: U89.16(7Q) U93.9(IN3)
NetU89_19: U89.19(8Q) U93.8(IN4)
NetU94_2: U94.2(1Q) U96.1(IN1)
NetU94_5: U94.5(2Q) U96.16(IN2)
NetU94_6: U94.6(3Q) U96.9(IN3)
NetU94_9: U94.9(4Q) U96.8(IN4)
NetU94_12: U94.12(5Q) U98.1(IN1)
NetU94_15: U94.15(6Q) U98.16(IN2)
NetU94_16: U94.16(7Q) U98.9(IN3)
NetU94_19: U94.19(8Q) U98.8(IN4)
NetU95_2: U95.2(1Q) U97.1(IN1)
NetU95_5: U95.5(2Q) U97.16(IN2)
NetU95_6: U95.6(3Q) U97.9(IN3)
NetU95_9: U95.9(4Q) U97.8(IN4)
NetU95_12: U95.12(5Q) U99.1(IN1)
NetU95_15: U95.15(6Q) U99.16(IN2)
NetU95_16: U95.16(7Q) U99.9(IN3)
NetU95_19: U95.19(8Q) U99.8(IN4)

Not connected (* = marked no-connect by the designer): U88 10(GND) 20(VCC); U89 10(GND) 20(VCC); U94 10(GND) 20(VCC); U95 10(GND) 20(VCC)

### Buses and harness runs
bus D[0..7] = port D[0..7]

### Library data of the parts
U88 U89 U94 U95 = 74ACT373_X: as U16 on sheet Latch1
U90-U93 U96-U99 = ADG439FBR_X: as U18 on sheet Latch1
